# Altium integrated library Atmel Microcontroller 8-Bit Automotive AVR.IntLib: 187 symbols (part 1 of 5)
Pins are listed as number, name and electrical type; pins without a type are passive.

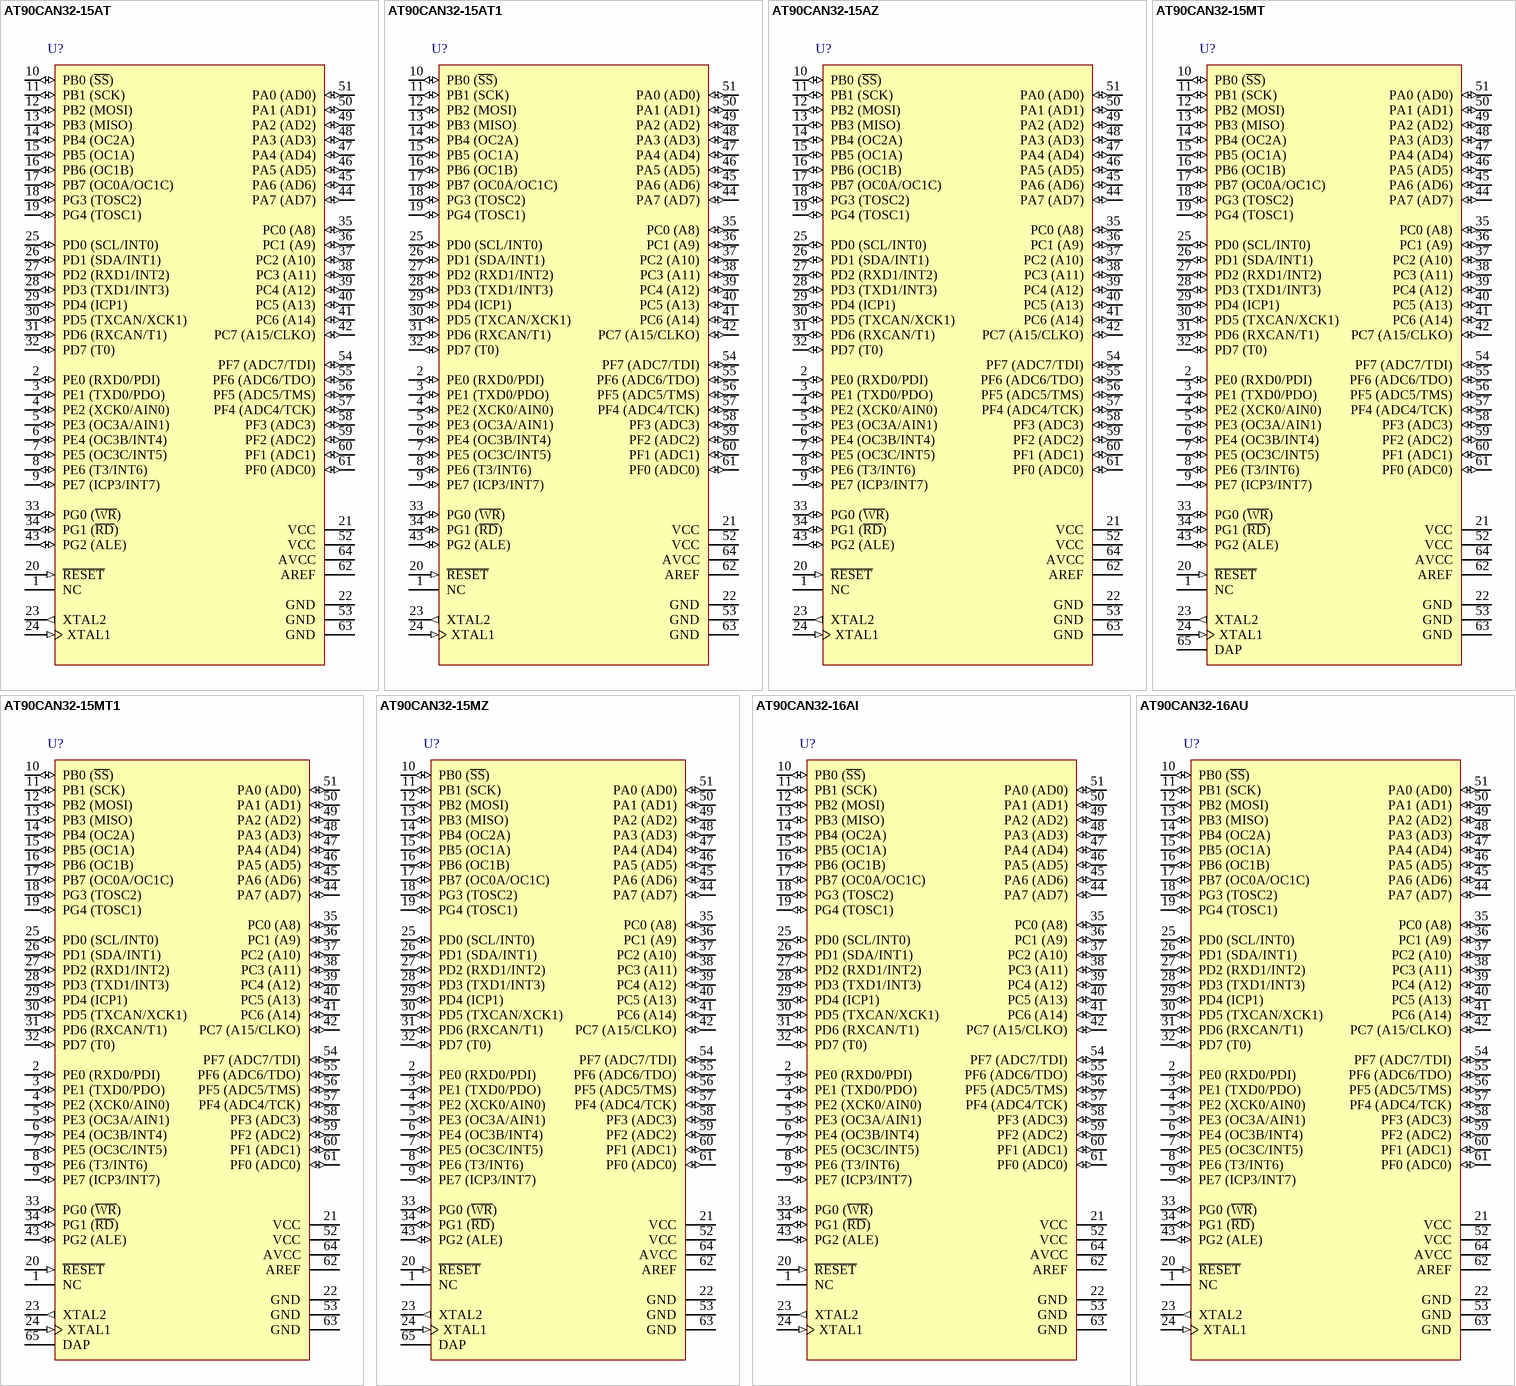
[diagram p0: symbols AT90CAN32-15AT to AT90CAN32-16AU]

## AT90CAN32-15AT
designator U?
8-bit Automotive AVR Microcontroller, 32KB Flash and CAN Controller, 53 GPIO pins, Automotive Grade (-40°to +85°C), 64-pin LQFP
footprint 64A_N (Thin QFP, 64-Leads, Body 14x14mm, Pitch 0.8mm, IPC Medium Density)
footprint 64A_L (Thin QFP, 64-Leads, Body 14x14mm, Pitch 0.8mm, IPC High Density)
footprint 64A_M (Thin QFP, 64-Leads, Body 14x14mm, Pitch 0.8mm, IPC Low Density)
pins: 1 NC, 2 PE0 (RXD0/PDI) (io), 3 PE1 (TXD0/PDO) (io), 4 PE2 (XCK0/AIN0) (io), 5 PE3 (OC3A/AIN1) (io), 6 PE4 (OC3B/INT4) (io), 7 PE5 (OC3C/INT5) (io), 8 PE6 (T3/INT6) (io), 9 PE7 (ICP3/INT7) (io), 10 PB0 (~{SS}) (io), 11 PB1 (SCK) (io), 12 PB2 (MOSI) (io), 13 PB3 (MISO) (io), 14 PB4 (OC2A) (io), 15 PB5 (OC1A) (io), 16 PB6 (OC1B) (io), 17 PB7 (OC0A/OC1C) (io), 18 PG3 (TOSC2) (io), 19 PG4 (TOSC1) (io), 20 ~{RESET} (in), 21 VCC (power), 22 GND (power), 23 XTAL2 (out), 24 XTAL1 (in), 25 PD0 (SCL/INT0) (io), 26 PD1 (SDA/INT1) (io), 27 PD2 (RXD1/INT2) (io), 28 PD3 (TXD1/INT3) (io), 29 PD4 (ICP1) (io), 30 PD5 (TXCAN/XCK1) (io), 31 PD6 (RXCAN/T1) (io), 32 PD7 (T0) (io), 33 PG0 (~{WR}) (io), 34 PG1 (~{RD}) (io), 35 PC0 (A8) (io), 36 PC1 (A9) (io), 37 PC2 (A10) (io), 38 PC3 (A11) (io), 39 PC4 (A12) (io), 40 PC5 (A13) (io), 41 PC6 (A14) (io), 42 PC7 (A15/CLKO) (io), 43 PG2 (ALE) (io), 44 PA7 (AD7) (io), 45 PA6 (AD6) (io), 46 PA5 (AD5) (io), 47 PA4 (AD4) (io), 48 PA3 (AD3) (io), 49 PA2 (AD2) (io), 50 PA1 (AD1) (io), 51 PA0 (AD0) (io), 52 VCC (power), 53 GND (power), 54 PF7 (ADC7/TDI) (io), 55 PF6 (ADC6/TDO) (io), 56 PF5 (ADC5/TMS) (io), 57 PF4 (ADC4/TCK) (io), 58 PF3 (ADC3) (io), 59 PF2 (ADC2) (io), 60 PF1 (ADC1) (io), 61 PF0 (ADC0) (io), 62 AREF (power), 63 GND (power), 64 AVCC (power)

## AT90CAN32-15AT1
designator U?
8-bit Automotive AVR Microcontroller, 32KB Flash and CAN Controller, 53 GPIO pins, Automotive Grade (-40°to +105°C), 64-pin LQFP
footprint 64A_N (Thin QFP, 64-Leads, Body 14x14mm, Pitch 0.8mm, IPC Medium Density)
footprint 64A_L (Thin QFP, 64-Leads, Body 14x14mm, Pitch 0.8mm, IPC High Density)
footprint 64A_M (Thin QFP, 64-Leads, Body 14x14mm, Pitch 0.8mm, IPC Low Density)
pins: 1 NC, 2 PE0 (RXD0/PDI) (io), 3 PE1 (TXD0/PDO) (io), 4 PE2 (XCK0/AIN0) (io), 5 PE3 (OC3A/AIN1) (io), 6 PE4 (OC3B/INT4) (io), 7 PE5 (OC3C/INT5) (io), 8 PE6 (T3/INT6) (io), 9 PE7 (ICP3/INT7) (io), 10 PB0 (~{SS}) (io), 11 PB1 (SCK) (io), 12 PB2 (MOSI) (io), 13 PB3 (MISO) (io), 14 PB4 (OC2A) (io), 15 PB5 (OC1A) (io), 16 PB6 (OC1B) (io), 17 PB7 (OC0A/OC1C) (io), 18 PG3 (TOSC2) (io), 19 PG4 (TOSC1) (io), 20 ~{RESET} (in), 21 VCC (power), 22 GND (power), 23 XTAL2 (out), 24 XTAL1 (in), 25 PD0 (SCL/INT0) (io), 26 PD1 (SDA/INT1) (io), 27 PD2 (RXD1/INT2) (io), 28 PD3 (TXD1/INT3) (io), 29 PD4 (ICP1) (io), 30 PD5 (TXCAN/XCK1) (io), 31 PD6 (RXCAN/T1) (io), 32 PD7 (T0) (io), 33 PG0 (~{WR}) (io), 34 PG1 (~{RD}) (io), 35 PC0 (A8) (io), 36 PC1 (A9) (io), 37 PC2 (A10) (io), 38 PC3 (A11) (io), 39 PC4 (A12) (io), 40 PC5 (A13) (io), 41 PC6 (A14) (io), 42 PC7 (A15/CLKO) (io), 43 PG2 (ALE) (io), 44 PA7 (AD7) (io), 45 PA6 (AD6) (io), 46 PA5 (AD5) (io), 47 PA4 (AD4) (io), 48 PA3 (AD3) (io), 49 PA2 (AD2) (io), 50 PA1 (AD1) (io), 51 PA0 (AD0) (io), 52 VCC (power), 53 GND (power), 54 PF7 (ADC7/TDI) (io), 55 PF6 (ADC6/TDO) (io), 56 PF5 (ADC5/TMS) (io), 57 PF4 (ADC4/TCK) (io), 58 PF3 (ADC3) (io), 59 PF2 (ADC2) (io), 60 PF1 (ADC1) (io), 61 PF0 (ADC0) (io), 62 AREF (power), 63 GND (power), 64 AVCC (power)

## AT90CAN32-15AZ
designator U?
8-bit Automotive AVR Microcontroller, 32KB Flash and CAN Controller, 53 GPIO pins, Automotive Grade (-40°to +125°C), 64-pin LQFP
footprint 64A_N (Thin QFP, 64-Leads, Body 14x14mm, Pitch 0.8mm, IPC Medium Density)
footprint 64A_L (Thin QFP, 64-Leads, Body 14x14mm, Pitch 0.8mm, IPC High Density)
footprint 64A_M (Thin QFP, 64-Leads, Body 14x14mm, Pitch 0.8mm, IPC Low Density)
pins: 1 NC, 2 PE0 (RXD0/PDI) (io), 3 PE1 (TXD0/PDO) (io), 4 PE2 (XCK0/AIN0) (io), 5 PE3 (OC3A/AIN1) (io), 6 PE4 (OC3B/INT4) (io), 7 PE5 (OC3C/INT5) (io), 8 PE6 (T3/INT6) (io), 9 PE7 (ICP3/INT7) (io), 10 PB0 (~{SS}) (io), 11 PB1 (SCK) (io), 12 PB2 (MOSI) (io), 13 PB3 (MISO) (io), 14 PB4 (OC2A) (io), 15 PB5 (OC1A) (io), 16 PB6 (OC1B) (io), 17 PB7 (OC0A/OC1C) (io), 18 PG3 (TOSC2) (io), 19 PG4 (TOSC1) (io), 20 ~{RESET} (in), 21 VCC (power), 22 GND (power), 23 XTAL2 (out), 24 XTAL1 (in), 25 PD0 (SCL/INT0) (io), 26 PD1 (SDA/INT1) (io), 27 PD2 (RXD1/INT2) (io), 28 PD3 (TXD1/INT3) (io), 29 PD4 (ICP1) (io), 30 PD5 (TXCAN/XCK1) (io), 31 PD6 (RXCAN/T1) (io), 32 PD7 (T0) (io), 33 PG0 (~{WR}) (io), 34 PG1 (~{RD}) (io), 35 PC0 (A8) (io), 36 PC1 (A9) (io), 37 PC2 (A10) (io), 38 PC3 (A11) (io), 39 PC4 (A12) (io), 40 PC5 (A13) (io), 41 PC6 (A14) (io), 42 PC7 (A15/CLKO) (io), 43 PG2 (ALE) (io), 44 PA7 (AD7) (io), 45 PA6 (AD6) (io), 46 PA5 (AD5) (io), 47 PA4 (AD4) (io), 48 PA3 (AD3) (io), 49 PA2 (AD2) (io), 50 PA1 (AD1) (io), 51 PA0 (AD0) (io), 52 VCC (power), 53 GND (power), 54 PF7 (ADC7/TDI) (io), 55 PF6 (ADC6/TDO) (io), 56 PF5 (ADC5/TMS) (io), 57 PF4 (ADC4/TCK) (io), 58 PF3 (ADC3) (io), 59 PF2 (ADC2) (io), 60 PF1 (ADC1) (io), 61 PF0 (ADC0) (io), 62 AREF (power), 63 GND (power), 64 AVCC (power)

## AT90CAN32-15MT
designator U?
8-bit Automotive AVR Microcontroller, 32KB Flash and CAN Controller, 53 GPIO pins, Automotive Grade (-40°to +85°C), 64-Pin VQFN
footprint Z64-1_N (QFN, 64-Leads, Body 9x9mm, Pitch 0.5mm, IPC Medium Density)
footprint Z64-1_L (QFN, 64-Leads, Body 9x9mm, Pitch 0.5mm, IPC High Density)
footprint Z64-1_M (QFN, 64-Leads, Body 9x9mm, Pitch 0.5mm, IPC Low Density)
pins: 1 NC, 2 PE0 (RXD0/PDI) (io), 3 PE1 (TXD0/PDO) (io), 4 PE2 (XCK0/AIN0) (io), 5 PE3 (OC3A/AIN1) (io), 6 PE4 (OC3B/INT4) (io), 7 PE5 (OC3C/INT5) (io), 8 PE6 (T3/INT6) (io), 9 PE7 (ICP3/INT7) (io), 10 PB0 (~{SS}) (io), 11 PB1 (SCK) (io), 12 PB2 (MOSI) (io), 13 PB3 (MISO) (io), 14 PB4 (OC2A) (io), 15 PB5 (OC1A) (io), 16 PB6 (OC1B) (io), 17 PB7 (OC0A/OC1C) (io), 18 PG3 (TOSC2) (io), 19 PG4 (TOSC1) (io), 20 ~{RESET} (in), 21 VCC (power), 22 GND (power), 23 XTAL2 (out), 24 XTAL1 (in), 25 PD0 (SCL/INT0) (io), 26 PD1 (SDA/INT1) (io), 27 PD2 (RXD1/INT2) (io), 28 PD3 (TXD1/INT3) (io), 29 PD4 (ICP1) (io), 30 PD5 (TXCAN/XCK1) (io), 31 PD6 (RXCAN/T1) (io), 32 PD7 (T0) (io), 33 PG0 (~{WR}) (io), 34 PG1 (~{RD}) (io), 35 PC0 (A8) (io), 36 PC1 (A9) (io), 37 PC2 (A10) (io), 38 PC3 (A11) (io), 39 PC4 (A12) (io), 40 PC5 (A13) (io), 41 PC6 (A14) (io), 42 PC7 (A15/CLKO) (io), 43 PG2 (ALE) (io), 44 PA7 (AD7) (io), 45 PA6 (AD6) (io), 46 PA5 (AD5) (io), 47 PA4 (AD4) (io), 48 PA3 (AD3) (io), 49 PA2 (AD2) (io), 50 PA1 (AD1) (io), 51 PA0 (AD0) (io), 52 VCC (power), 53 GND (power), 54 PF7 (ADC7/TDI) (io), 55 PF6 (ADC6/TDO) (io), 56 PF5 (ADC5/TMS) (io), 57 PF4 (ADC4/TCK) (io), 58 PF3 (ADC3) (io), 59 PF2 (ADC2) (io), 60 PF1 (ADC1) (io), 61 PF0 (ADC0) (io), 62 AREF (power), 63 GND (power), 64 AVCC (power), 65 DAP (power)

## AT90CAN32-15MT1
designator U?
8-bit Automotive AVR Microcontroller, 32KB Flash and CAN Controller, 53 GPIO pins, Automotive Grade (-40°to +105C), 64-Pin VQFN
footprint Z64-1_N (QFN, 64-Leads, Body 9x9mm, Pitch 0.5mm, IPC Medium Density)
footprint Z64-1_L (QFN, 64-Leads, Body 9x9mm, Pitch 0.5mm, IPC High Density)
footprint Z64-1_M (QFN, 64-Leads, Body 9x9mm, Pitch 0.5mm, IPC Low Density)
pins: 1 NC, 2 PE0 (RXD0/PDI) (io), 3 PE1 (TXD0/PDO) (io), 4 PE2 (XCK0/AIN0) (io), 5 PE3 (OC3A/AIN1) (io), 6 PE4 (OC3B/INT4) (io), 7 PE5 (OC3C/INT5) (io), 8 PE6 (T3/INT6) (io), 9 PE7 (ICP3/INT7) (io), 10 PB0 (~{SS}) (io), 11 PB1 (SCK) (io), 12 PB2 (MOSI) (io), 13 PB3 (MISO) (io), 14 PB4 (OC2A) (io), 15 PB5 (OC1A) (io), 16 PB6 (OC1B) (io), 17 PB7 (OC0A/OC1C) (io), 18 PG3 (TOSC2) (io), 19 PG4 (TOSC1) (io), 20 ~{RESET} (in), 21 VCC (power), 22 GND (power), 23 XTAL2 (out), 24 XTAL1 (in), 25 PD0 (SCL/INT0) (io), 26 PD1 (SDA/INT1) (io), 27 PD2 (RXD1/INT2) (io), 28 PD3 (TXD1/INT3) (io), 29 PD4 (ICP1) (io), 30 PD5 (TXCAN/XCK1) (io), 31 PD6 (RXCAN/T1) (io), 32 PD7 (T0) (io), 33 PG0 (~{WR}) (io), 34 PG1 (~{RD}) (io), 35 PC0 (A8) (io), 36 PC1 (A9) (io), 37 PC2 (A10) (io), 38 PC3 (A11) (io), 39 PC4 (A12) (io), 40 PC5 (A13) (io), 41 PC6 (A14) (io), 42 PC7 (A15/CLKO) (io), 43 PG2 (ALE) (io), 44 PA7 (AD7) (io), 45 PA6 (AD6) (io), 46 PA5 (AD5) (io), 47 PA4 (AD4) (io), 48 PA3 (AD3) (io), 49 PA2 (AD2) (io), 50 PA1 (AD1) (io), 51 PA0 (AD0) (io), 52 VCC (power), 53 GND (power), 54 PF7 (ADC7/TDI) (io), 55 PF6 (ADC6/TDO) (io), 56 PF5 (ADC5/TMS) (io), 57 PF4 (ADC4/TCK) (io), 58 PF3 (ADC3) (io), 59 PF2 (ADC2) (io), 60 PF1 (ADC1) (io), 61 PF0 (ADC0) (io), 62 AREF (power), 63 GND (power), 64 AVCC (power), 65 DAP (power)

## AT90CAN32-15MZ
designator U?
8-bit Automotive AVR Microcontroller, 32KB Flash and CAN Controller, 53 GPIO pins, Automotive Grade (-40°to +125°C), 64-Pin VQFN
footprint Z64-1_N (QFN, 64-Leads, Body 9x9mm, Pitch 0.5mm, IPC Medium Density)
footprint Z64-1_L (QFN, 64-Leads, Body 9x9mm, Pitch 0.5mm, IPC High Density)
footprint Z64-1_M (QFN, 64-Leads, Body 9x9mm, Pitch 0.5mm, IPC Low Density)
pins: 1 NC, 2 PE0 (RXD0/PDI) (io), 3 PE1 (TXD0/PDO) (io), 4 PE2 (XCK0/AIN0) (io), 5 PE3 (OC3A/AIN1) (io), 6 PE4 (OC3B/INT4) (io), 7 PE5 (OC3C/INT5) (io), 8 PE6 (T3/INT6) (io), 9 PE7 (ICP3/INT7) (io), 10 PB0 (~{SS}) (io), 11 PB1 (SCK) (io), 12 PB2 (MOSI) (io), 13 PB3 (MISO) (io), 14 PB4 (OC2A) (io), 15 PB5 (OC1A) (io), 16 PB6 (OC1B) (io), 17 PB7 (OC0A/OC1C) (io), 18 PG3 (TOSC2) (io), 19 PG4 (TOSC1) (io), 20 ~{RESET} (in), 21 VCC (power), 22 GND (power), 23 XTAL2 (out), 24 XTAL1 (in), 25 PD0 (SCL/INT0) (io), 26 PD1 (SDA/INT1) (io), 27 PD2 (RXD1/INT2) (io), 28 PD3 (TXD1/INT3) (io), 29 PD4 (ICP1) (io), 30 PD5 (TXCAN/XCK1) (io), 31 PD6 (RXCAN/T1) (io), 32 PD7 (T0) (io), 33 PG0 (~{WR}) (io), 34 PG1 (~{RD}) (io), 35 PC0 (A8) (io), 36 PC1 (A9) (io), 37 PC2 (A10) (io), 38 PC3 (A11) (io), 39 PC4 (A12) (io), 40 PC5 (A13) (io), 41 PC6 (A14) (io), 42 PC7 (A15/CLKO) (io), 43 PG2 (ALE) (io), 44 PA7 (AD7) (io), 45 PA6 (AD6) (io), 46 PA5 (AD5) (io), 47 PA4 (AD4) (io), 48 PA3 (AD3) (io), 49 PA2 (AD2) (io), 50 PA1 (AD1) (io), 51 PA0 (AD0) (io), 52 VCC (power), 53 GND (power), 54 PF7 (ADC7/TDI) (io), 55 PF6 (ADC6/TDO) (io), 56 PF5 (ADC5/TMS) (io), 57 PF4 (ADC4/TCK) (io), 58 PF3 (ADC3) (io), 59 PF2 (ADC2) (io), 60 PF1 (ADC1) (io), 61 PF0 (ADC0) (io), 62 AREF (power), 63 GND (power), 64 AVCC (power), 65 DAP (power)

## AT90CAN32-16AI
designator U?
8-bit AVR Microcontroller, 32KB Flash and CAN Controller, 53 GPIO pins, Industrial Grade (-40° to +85°C), 64-pin LQFP
footprint 64A_N (Thin QFP, 64-Leads, Body 14x14mm, Pitch 0.8mm, IPC Medium Density)
footprint 64A_L (Thin QFP, 64-Leads, Body 14x14mm, Pitch 0.8mm, IPC High Density)
footprint 64A_M (Thin QFP, 64-Leads, Body 14x14mm, Pitch 0.8mm, IPC Low Density)
pins: 1 NC, 2 PE0 (RXD0/PDI) (io), 3 PE1 (TXD0/PDO) (io), 4 PE2 (XCK0/AIN0) (io), 5 PE3 (OC3A/AIN1) (io), 6 PE4 (OC3B/INT4) (io), 7 PE5 (OC3C/INT5) (io), 8 PE6 (T3/INT6) (io), 9 PE7 (ICP3/INT7) (io), 10 PB0 (~{SS}) (io), 11 PB1 (SCK) (io), 12 PB2 (MOSI) (io), 13 PB3 (MISO) (io), 14 PB4 (OC2A) (io), 15 PB5 (OC1A) (io), 16 PB6 (OC1B) (io), 17 PB7 (OC0A/OC1C) (io), 18 PG3 (TOSC2) (io), 19 PG4 (TOSC1) (io), 20 ~{RESET} (in), 21 VCC (power), 22 GND (power), 23 XTAL2 (out), 24 XTAL1 (in), 25 PD0 (SCL/INT0) (io), 26 PD1 (SDA/INT1) (io), 27 PD2 (RXD1/INT2) (io), 28 PD3 (TXD1/INT3) (io), 29 PD4 (ICP1) (io), 30 PD5 (TXCAN/XCK1) (io), 31 PD6 (RXCAN/T1) (io), 32 PD7 (T0) (io), 33 PG0 (~{WR}) (io), 34 PG1 (~{RD}) (io), 35 PC0 (A8) (io), 36 PC1 (A9) (io), 37 PC2 (A10) (io), 38 PC3 (A11) (io), 39 PC4 (A12) (io), 40 PC5 (A13) (io), 41 PC6 (A14) (io), 42 PC7 (A15/CLKO) (io), 43 PG2 (ALE) (io), 44 PA7 (AD7) (io), 45 PA6 (AD6) (io), 46 PA5 (AD5) (io), 47 PA4 (AD4) (io), 48 PA3 (AD3) (io), 49 PA2 (AD2) (io), 50 PA1 (AD1) (io), 51 PA0 (AD0) (io), 52 VCC (power), 53 GND (power), 54 PF7 (ADC7/TDI) (io), 55 PF6 (ADC6/TDO) (io), 56 PF5 (ADC5/TMS) (io), 57 PF4 (ADC4/TCK) (io), 58 PF3 (ADC3) (io), 59 PF2 (ADC2) (io), 60 PF1 (ADC1) (io), 61 PF0 (ADC0) (io), 62 AREF (power), 63 GND (power), 64 AVCC (power)

## AT90CAN32-16AU
designator U?
8-bit AVR Microcontroller, 32KB Flash and CAN Controller, 53 GPIO pins, Industrial Grade (-40° to +85°C), 64-pin LQFP, Green
footprint 64A_N (Thin QFP, 64-Leads, Body 14x14mm, Pitch 0.8mm, IPC Medium Density)
footprint 64A_L (Thin QFP, 64-Leads, Body 14x14mm, Pitch 0.8mm, IPC High Density)
footprint 64A_M (Thin QFP, 64-Leads, Body 14x14mm, Pitch 0.8mm, IPC Low Density)
pins: 1 NC, 2 PE0 (RXD0/PDI) (io), 3 PE1 (TXD0/PDO) (io), 4 PE2 (XCK0/AIN0) (io), 5 PE3 (OC3A/AIN1) (io), 6 PE4 (OC3B/INT4) (io), 7 PE5 (OC3C/INT5) (io), 8 PE6 (T3/INT6) (io), 9 PE7 (ICP3/INT7) (io), 10 PB0 (~{SS}) (io), 11 PB1 (SCK) (io), 12 PB2 (MOSI) (io), 13 PB3 (MISO) (io), 14 PB4 (OC2A) (io), 15 PB5 (OC1A) (io), 16 PB6 (OC1B) (io), 17 PB7 (OC0A/OC1C) (io), 18 PG3 (TOSC2) (io), 19 PG4 (TOSC1) (io), 20 ~{RESET} (in), 21 VCC (power), 22 GND (power), 23 XTAL2 (out), 24 XTAL1 (in), 25 PD0 (SCL/INT0) (io), 26 PD1 (SDA/INT1) (io), 27 PD2 (RXD1/INT2) (io), 28 PD3 (TXD1/INT3) (io), 29 PD4 (ICP1) (io), 30 PD5 (TXCAN/XCK1) (io), 31 PD6 (RXCAN/T1) (io), 32 PD7 (T0) (io), 33 PG0 (~{WR}) (io), 34 PG1 (~{RD}) (io), 35 PC0 (A8) (io), 36 PC1 (A9) (io), 37 PC2 (A10) (io), 38 PC3 (A11) (io), 39 PC4 (A12) (io), 40 PC5 (A13) (io), 41 PC6 (A14) (io), 42 PC7 (A15/CLKO) (io), 43 PG2 (ALE) (io), 44 PA7 (AD7) (io), 45 PA6 (AD6) (io), 46 PA5 (AD5) (io), 47 PA4 (AD4) (io), 48 PA3 (AD3) (io), 49 PA2 (AD2) (io), 50 PA1 (AD1) (io), 51 PA0 (AD0) (io), 52 VCC (power), 53 GND (power), 54 PF7 (ADC7/TDI) (io), 55 PF6 (ADC6/TDO) (io), 56 PF5 (ADC5/TMS) (io), 57 PF4 (ADC4/TCK) (io), 58 PF3 (ADC3) (io), 59 PF2 (ADC2) (io), 60 PF1 (ADC1) (io), 61 PF0 (ADC0) (io), 62 AREF (power), 63 GND (power), 64 AVCC (power)

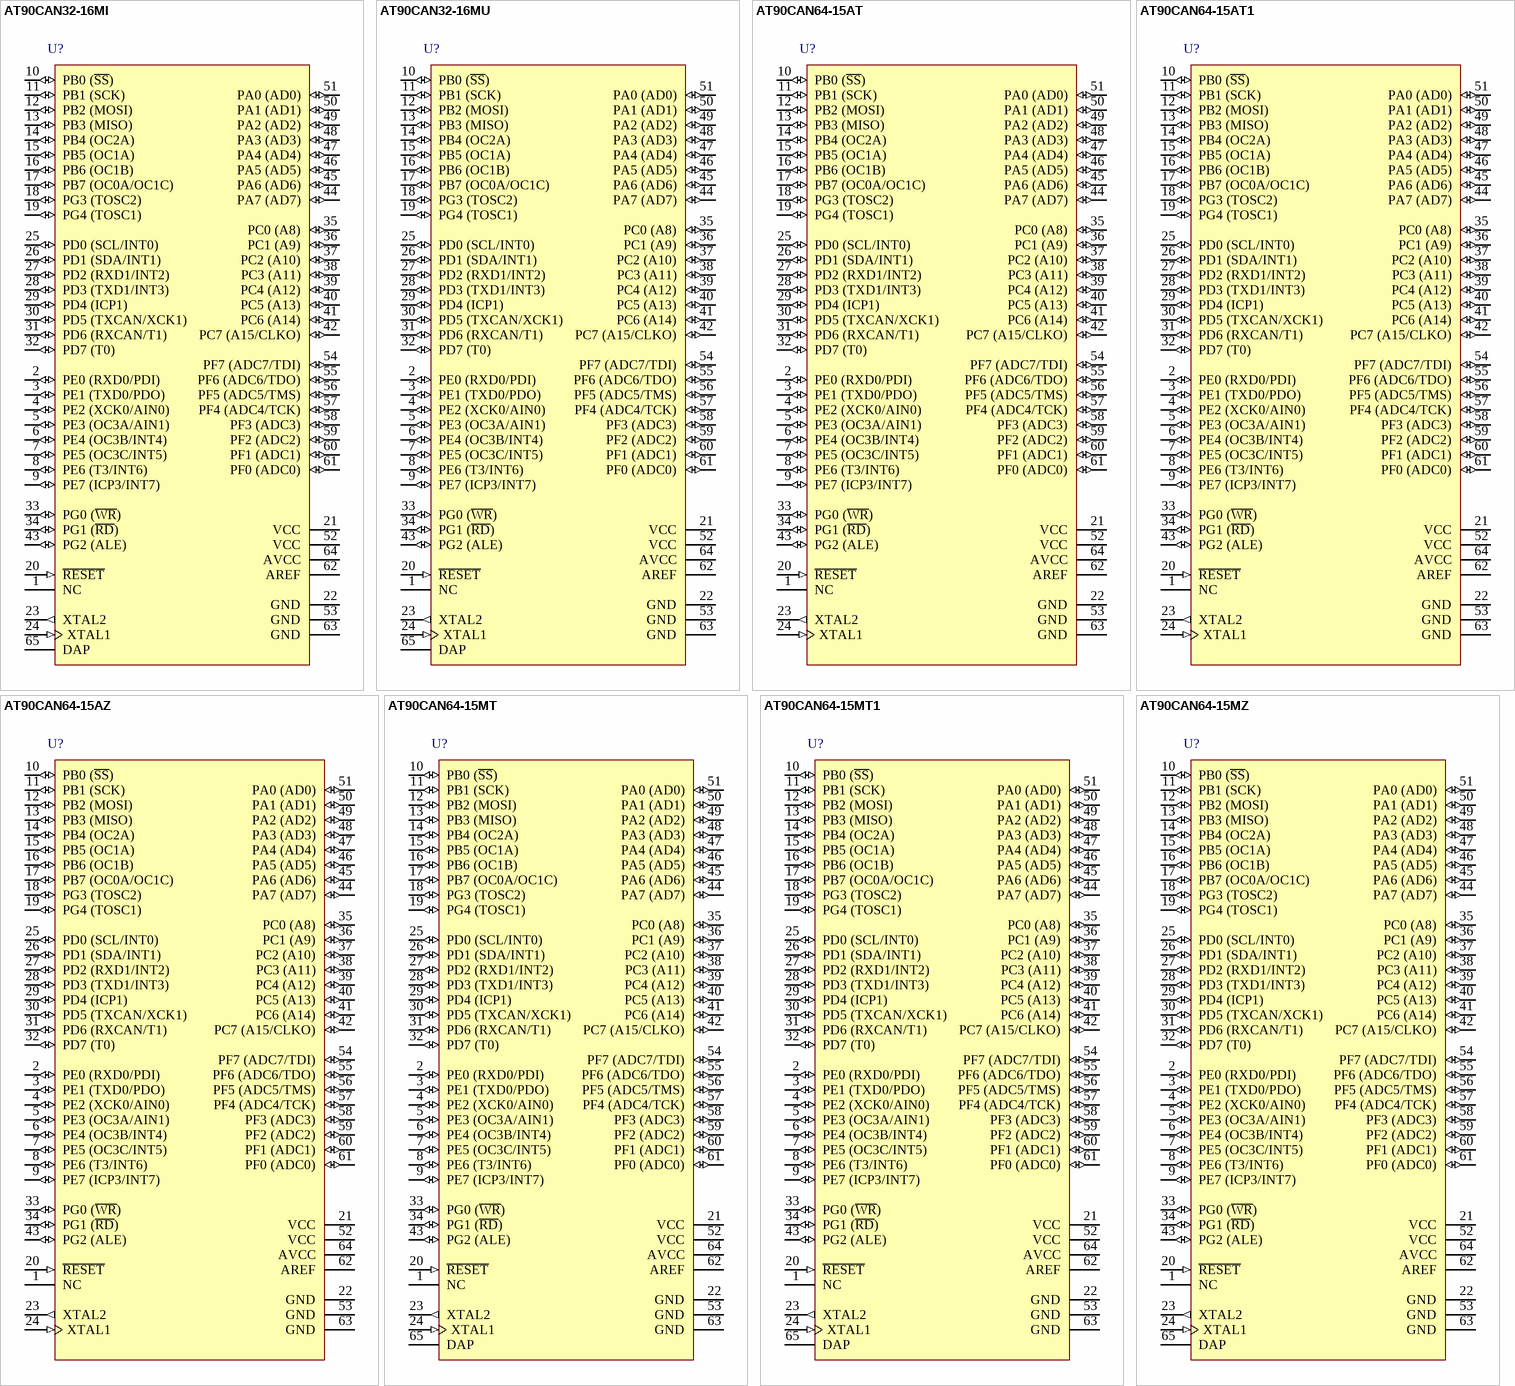
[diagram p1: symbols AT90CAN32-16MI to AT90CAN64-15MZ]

## AT90CAN32-16MI
designator U?
8-bit AVR Microcontroller, 32KB Flash and CAN Controller, 53 GPIO pins, Industrial Grade (-40° to +85°C), 64-pin VQFN
footprint Z64-1_N (QFN, 64-Leads, Body 9x9mm, Pitch 0.5mm, IPC Medium Density)
footprint Z64-1_L (QFN, 64-Leads, Body 9x9mm, Pitch 0.5mm, IPC High Density)
footprint Z64-1_M (QFN, 64-Leads, Body 9x9mm, Pitch 0.5mm, IPC Low Density)
pins: 1 NC, 2 PE0 (RXD0/PDI) (io), 3 PE1 (TXD0/PDO) (io), 4 PE2 (XCK0/AIN0) (io), 5 PE3 (OC3A/AIN1) (io), 6 PE4 (OC3B/INT4) (io), 7 PE5 (OC3C/INT5) (io), 8 PE6 (T3/INT6) (io), 9 PE7 (ICP3/INT7) (io), 10 PB0 (~{SS}) (io), 11 PB1 (SCK) (io), 12 PB2 (MOSI) (io), 13 PB3 (MISO) (io), 14 PB4 (OC2A) (io), 15 PB5 (OC1A) (io), 16 PB6 (OC1B) (io), 17 PB7 (OC0A/OC1C) (io), 18 PG3 (TOSC2) (io), 19 PG4 (TOSC1) (io), 20 ~{RESET} (in), 21 VCC (power), 22 GND (power), 23 XTAL2 (out), 24 XTAL1 (in), 25 PD0 (SCL/INT0) (io), 26 PD1 (SDA/INT1) (io), 27 PD2 (RXD1/INT2) (io), 28 PD3 (TXD1/INT3) (io), 29 PD4 (ICP1) (io), 30 PD5 (TXCAN/XCK1) (io), 31 PD6 (RXCAN/T1) (io), 32 PD7 (T0) (io), 33 PG0 (~{WR}) (io), 34 PG1 (~{RD}) (io), 35 PC0 (A8) (io), 36 PC1 (A9) (io), 37 PC2 (A10) (io), 38 PC3 (A11) (io), 39 PC4 (A12) (io), 40 PC5 (A13) (io), 41 PC6 (A14) (io), 42 PC7 (A15/CLKO) (io), 43 PG2 (ALE) (io), 44 PA7 (AD7) (io), 45 PA6 (AD6) (io), 46 PA5 (AD5) (io), 47 PA4 (AD4) (io), 48 PA3 (AD3) (io), 49 PA2 (AD2) (io), 50 PA1 (AD1) (io), 51 PA0 (AD0) (io), 52 VCC (power), 53 GND (power), 54 PF7 (ADC7/TDI) (io), 55 PF6 (ADC6/TDO) (io), 56 PF5 (ADC5/TMS) (io), 57 PF4 (ADC4/TCK) (io), 58 PF3 (ADC3) (io), 59 PF2 (ADC2) (io), 60 PF1 (ADC1) (io), 61 PF0 (ADC0) (io), 62 AREF (power), 63 GND (power), 64 AVCC (power), 65 DAP (power)

## AT90CAN32-16MU
designator U?
8-bit AVR Microcontroller, 32KB Flash and CAN Controller, 53 GPIO pins, Industrial Grade (-40° to +85°C), 64-pin VQFN, Green
footprint Z64-1_N (QFN, 64-Leads, Body 9x9mm, Pitch 0.5mm, IPC Medium Density)
footprint Z64-1_L (QFN, 64-Leads, Body 9x9mm, Pitch 0.5mm, IPC High Density)
footprint Z64-1_M (QFN, 64-Leads, Body 9x9mm, Pitch 0.5mm, IPC Low Density)
pins: 1 NC, 2 PE0 (RXD0/PDI) (io), 3 PE1 (TXD0/PDO) (io), 4 PE2 (XCK0/AIN0) (io), 5 PE3 (OC3A/AIN1) (io), 6 PE4 (OC3B/INT4) (io), 7 PE5 (OC3C/INT5) (io), 8 PE6 (T3/INT6) (io), 9 PE7 (ICP3/INT7) (io), 10 PB0 (~{SS}) (io), 11 PB1 (SCK) (io), 12 PB2 (MOSI) (io), 13 PB3 (MISO) (io), 14 PB4 (OC2A) (io), 15 PB5 (OC1A) (io), 16 PB6 (OC1B) (io), 17 PB7 (OC0A/OC1C) (io), 18 PG3 (TOSC2) (io), 19 PG4 (TOSC1) (io), 20 ~{RESET} (in), 21 VCC (power), 22 GND (power), 23 XTAL2 (out), 24 XTAL1 (in), 25 PD0 (SCL/INT0) (io), 26 PD1 (SDA/INT1) (io), 27 PD2 (RXD1/INT2) (io), 28 PD3 (TXD1/INT3) (io), 29 PD4 (ICP1) (io), 30 PD5 (TXCAN/XCK1) (io), 31 PD6 (RXCAN/T1) (io), 32 PD7 (T0) (io), 33 PG0 (~{WR}) (io), 34 PG1 (~{RD}) (io), 35 PC0 (A8) (io), 36 PC1 (A9) (io), 37 PC2 (A10) (io), 38 PC3 (A11) (io), 39 PC4 (A12) (io), 40 PC5 (A13) (io), 41 PC6 (A14) (io), 42 PC7 (A15/CLKO) (io), 43 PG2 (ALE) (io), 44 PA7 (AD7) (io), 45 PA6 (AD6) (io), 46 PA5 (AD5) (io), 47 PA4 (AD4) (io), 48 PA3 (AD3) (io), 49 PA2 (AD2) (io), 50 PA1 (AD1) (io), 51 PA0 (AD0) (io), 52 VCC (power), 53 GND (power), 54 PF7 (ADC7/TDI) (io), 55 PF6 (ADC6/TDO) (io), 56 PF5 (ADC5/TMS) (io), 57 PF4 (ADC4/TCK) (io), 58 PF3 (ADC3) (io), 59 PF2 (ADC2) (io), 60 PF1 (ADC1) (io), 61 PF0 (ADC0) (io), 62 AREF (power), 63 GND (power), 64 AVCC (power), 65 DAP (power)

## AT90CAN64-15AT
designator U?
8-bit Automotive AVR Microcontroller, 64KB Flash and CAN Controller, 53 GPIO pins, Automotive Grade (-40°to +85°C), 64-pin LQFP
footprint 64A_N (Thin QFP, 64-Leads, Body 14x14mm, Pitch 0.8mm, IPC Medium Density)
footprint 64A_L (Thin QFP, 64-Leads, Body 14x14mm, Pitch 0.8mm, IPC High Density)
footprint 64A_M (Thin QFP, 64-Leads, Body 14x14mm, Pitch 0.8mm, IPC Low Density)
pins: 1 NC, 2 PE0 (RXD0/PDI) (io), 3 PE1 (TXD0/PDO) (io), 4 PE2 (XCK0/AIN0) (io), 5 PE3 (OC3A/AIN1) (io), 6 PE4 (OC3B/INT4) (io), 7 PE5 (OC3C/INT5) (io), 8 PE6 (T3/INT6) (io), 9 PE7 (ICP3/INT7) (io), 10 PB0 (~{SS}) (io), 11 PB1 (SCK) (io), 12 PB2 (MOSI) (io), 13 PB3 (MISO) (io), 14 PB4 (OC2A) (io), 15 PB5 (OC1A) (io), 16 PB6 (OC1B) (io), 17 PB7 (OC0A/OC1C) (io), 18 PG3 (TOSC2) (io), 19 PG4 (TOSC1) (io), 20 ~{RESET} (in), 21 VCC (power), 22 GND (power), 23 XTAL2 (out), 24 XTAL1 (in), 25 PD0 (SCL/INT0) (io), 26 PD1 (SDA/INT1) (io), 27 PD2 (RXD1/INT2) (io), 28 PD3 (TXD1/INT3) (io), 29 PD4 (ICP1) (io), 30 PD5 (TXCAN/XCK1) (io), 31 PD6 (RXCAN/T1) (io), 32 PD7 (T0) (io), 33 PG0 (~{WR}) (io), 34 PG1 (~{RD}) (io), 35 PC0 (A8) (io), 36 PC1 (A9) (io), 37 PC2 (A10) (io), 38 PC3 (A11) (io), 39 PC4 (A12) (io), 40 PC5 (A13) (io), 41 PC6 (A14) (io), 42 PC7 (A15/CLKO) (io), 43 PG2 (ALE) (io), 44 PA7 (AD7) (io), 45 PA6 (AD6) (io), 46 PA5 (AD5) (io), 47 PA4 (AD4) (io), 48 PA3 (AD3) (io), 49 PA2 (AD2) (io), 50 PA1 (AD1) (io), 51 PA0 (AD0) (io), 52 VCC (power), 53 GND (power), 54 PF7 (ADC7/TDI) (io), 55 PF6 (ADC6/TDO) (io), 56 PF5 (ADC5/TMS) (io), 57 PF4 (ADC4/TCK) (io), 58 PF3 (ADC3) (io), 59 PF2 (ADC2) (io), 60 PF1 (ADC1) (io), 61 PF0 (ADC0) (io), 62 AREF (power), 63 GND (power), 64 AVCC (power)

## AT90CAN64-15AT1
designator U?
8-bit Automotive AVR Microcontroller, 64KB Flash and CAN Controller, 53 GPIO pins, Automotive Grade (-40°to +105°C), 64-pin LQFP
footprint 64A_N (Thin QFP, 64-Leads, Body 14x14mm, Pitch 0.8mm, IPC Medium Density)
footprint 64A_L (Thin QFP, 64-Leads, Body 14x14mm, Pitch 0.8mm, IPC High Density)
footprint 64A_M (Thin QFP, 64-Leads, Body 14x14mm, Pitch 0.8mm, IPC Low Density)
pins: 1 NC, 2 PE0 (RXD0/PDI) (io), 3 PE1 (TXD0/PDO) (io), 4 PE2 (XCK0/AIN0) (io), 5 PE3 (OC3A/AIN1) (io), 6 PE4 (OC3B/INT4) (io), 7 PE5 (OC3C/INT5) (io), 8 PE6 (T3/INT6) (io), 9 PE7 (ICP3/INT7) (io), 10 PB0 (~{SS}) (io), 11 PB1 (SCK) (io), 12 PB2 (MOSI) (io), 13 PB3 (MISO) (io), 14 PB4 (OC2A) (io), 15 PB5 (OC1A) (io), 16 PB6 (OC1B) (io), 17 PB7 (OC0A/OC1C) (io), 18 PG3 (TOSC2) (io), 19 PG4 (TOSC1) (io), 20 ~{RESET} (in), 21 VCC (power), 22 GND (power), 23 XTAL2 (out), 24 XTAL1 (in), 25 PD0 (SCL/INT0) (io), 26 PD1 (SDA/INT1) (io), 27 PD2 (RXD1/INT2) (io), 28 PD3 (TXD1/INT3) (io), 29 PD4 (ICP1) (io), 30 PD5 (TXCAN/XCK1) (io), 31 PD6 (RXCAN/T1) (io), 32 PD7 (T0) (io), 33 PG0 (~{WR}) (io), 34 PG1 (~{RD}) (io), 35 PC0 (A8) (io), 36 PC1 (A9) (io), 37 PC2 (A10) (io), 38 PC3 (A11) (io), 39 PC4 (A12) (io), 40 PC5 (A13) (io), 41 PC6 (A14) (io), 42 PC7 (A15/CLKO) (io), 43 PG2 (ALE) (io), 44 PA7 (AD7) (io), 45 PA6 (AD6) (io), 46 PA5 (AD5) (io), 47 PA4 (AD4) (io), 48 PA3 (AD3) (io), 49 PA2 (AD2) (io), 50 PA1 (AD1) (io), 51 PA0 (AD0) (io), 52 VCC (power), 53 GND (power), 54 PF7 (ADC7/TDI) (io), 55 PF6 (ADC6/TDO) (io), 56 PF5 (ADC5/TMS) (io), 57 PF4 (ADC4/TCK) (io), 58 PF3 (ADC3) (io), 59 PF2 (ADC2) (io), 60 PF1 (ADC1) (io), 61 PF0 (ADC0) (io), 62 AREF (power), 63 GND (power), 64 AVCC (power)

## AT90CAN64-15AZ
designator U?
8-bit Automotive AVR Microcontroller, 64KB Flash and CAN Controller, 53 GPIO pins, Automotive Grade (-40°to +125°C), 64-pin LQFP
footprint 64A_N (Thin QFP, 64-Leads, Body 14x14mm, Pitch 0.8mm, IPC Medium Density)
footprint 64A_L (Thin QFP, 64-Leads, Body 14x14mm, Pitch 0.8mm, IPC High Density)
footprint 64A_M (Thin QFP, 64-Leads, Body 14x14mm, Pitch 0.8mm, IPC Low Density)
pins: 1 NC, 2 PE0 (RXD0/PDI) (io), 3 PE1 (TXD0/PDO) (io), 4 PE2 (XCK0/AIN0) (io), 5 PE3 (OC3A/AIN1) (io), 6 PE4 (OC3B/INT4) (io), 7 PE5 (OC3C/INT5) (io), 8 PE6 (T3/INT6) (io), 9 PE7 (ICP3/INT7) (io), 10 PB0 (~{SS}) (io), 11 PB1 (SCK) (io), 12 PB2 (MOSI) (io), 13 PB3 (MISO) (io), 14 PB4 (OC2A) (io), 15 PB5 (OC1A) (io), 16 PB6 (OC1B) (io), 17 PB7 (OC0A/OC1C) (io), 18 PG3 (TOSC2) (io), 19 PG4 (TOSC1) (io), 20 ~{RESET} (in), 21 VCC (power), 22 GND (power), 23 XTAL2 (out), 24 XTAL1 (in), 25 PD0 (SCL/INT0) (io), 26 PD1 (SDA/INT1) (io), 27 PD2 (RXD1/INT2) (io), 28 PD3 (TXD1/INT3) (io), 29 PD4 (ICP1) (io), 30 PD5 (TXCAN/XCK1) (io), 31 PD6 (RXCAN/T1) (io), 32 PD7 (T0) (io), 33 PG0 (~{WR}) (io), 34 PG1 (~{RD}) (io), 35 PC0 (A8) (io), 36 PC1 (A9) (io), 37 PC2 (A10) (io), 38 PC3 (A11) (io), 39 PC4 (A12) (io), 40 PC5 (A13) (io), 41 PC6 (A14) (io), 42 PC7 (A15/CLKO) (io), 43 PG2 (ALE) (io), 44 PA7 (AD7) (io), 45 PA6 (AD6) (io), 46 PA5 (AD5) (io), 47 PA4 (AD4) (io), 48 PA3 (AD3) (io), 49 PA2 (AD2) (io), 50 PA1 (AD1) (io), 51 PA0 (AD0) (io), 52 VCC (power), 53 GND (power), 54 PF7 (ADC7/TDI) (io), 55 PF6 (ADC6/TDO) (io), 56 PF5 (ADC5/TMS) (io), 57 PF4 (ADC4/TCK) (io), 58 PF3 (ADC3) (io), 59 PF2 (ADC2) (io), 60 PF1 (ADC1) (io), 61 PF0 (ADC0) (io), 62 AREF (power), 63 GND (power), 64 AVCC (power)

## AT90CAN64-15MT
designator U?
8-bit Automotive AVR Microcontroller, 64KB Flash and CAN Controller, 53 GPIO pins, Automotive Grade (-40°to +85°C), 64-Pin VQFN
footprint Z64-2_N (QFN, 64-Leads, Body 9x9mm, Pitch 0.5mm, IPC Medium Density)
footprint Z64-2_L (QFN, 64-Leads, Body 9x9mm, Pitch 0.5mm, IPC High Density)
footprint Z64-2_M (QFN, 64-Leads, Body 9x9mm, Pitch 0.5mm, IPC Low Density)
pins: 1 NC, 2 PE0 (RXD0/PDI) (io), 3 PE1 (TXD0/PDO) (io), 4 PE2 (XCK0/AIN0) (io), 5 PE3 (OC3A/AIN1) (io), 6 PE4 (OC3B/INT4) (io), 7 PE5 (OC3C/INT5) (io), 8 PE6 (T3/INT6) (io), 9 PE7 (ICP3/INT7) (io), 10 PB0 (~{SS}) (io), 11 PB1 (SCK) (io), 12 PB2 (MOSI) (io), 13 PB3 (MISO) (io), 14 PB4 (OC2A) (io), 15 PB5 (OC1A) (io), 16 PB6 (OC1B) (io), 17 PB7 (OC0A/OC1C) (io), 18 PG3 (TOSC2) (io), 19 PG4 (TOSC1) (io), 20 ~{RESET} (in), 21 VCC (power), 22 GND (power), 23 XTAL2 (out), 24 XTAL1 (in), 25 PD0 (SCL/INT0) (io), 26 PD1 (SDA/INT1) (io), 27 PD2 (RXD1/INT2) (io), 28 PD3 (TXD1/INT3) (io), 29 PD4 (ICP1) (io), 30 PD5 (TXCAN/XCK1) (io), 31 PD6 (RXCAN/T1) (io), 32 PD7 (T0) (io), 33 PG0 (~{WR}) (io), 34 PG1 (~{RD}) (io), 35 PC0 (A8) (io), 36 PC1 (A9) (io), 37 PC2 (A10) (io), 38 PC3 (A11) (io), 39 PC4 (A12) (io), 40 PC5 (A13) (io), 41 PC6 (A14) (io), 42 PC7 (A15/CLKO) (io), 43 PG2 (ALE) (io), 44 PA7 (AD7) (io), 45 PA6 (AD6) (io), 46 PA5 (AD5) (io), 47 PA4 (AD4) (io), 48 PA3 (AD3) (io), 49 PA2 (AD2) (io), 50 PA1 (AD1) (io), 51 PA0 (AD0) (io), 52 VCC (power), 53 GND (power), 54 PF7 (ADC7/TDI) (io), 55 PF6 (ADC6/TDO) (io), 56 PF5 (ADC5/TMS) (io), 57 PF4 (ADC4/TCK) (io), 58 PF3 (ADC3) (io), 59 PF2 (ADC2) (io), 60 PF1 (ADC1) (io), 61 PF0 (ADC0) (io), 62 AREF (power), 63 GND (power), 64 AVCC (power), 65 DAP (power)

## AT90CAN64-15MT1
designator U?
8-bit Automotive AVR Microcontroller, 64KB Flash and CAN Controller, 53 GPIO pins, Automotive Grade (-40°to +105C), 64-Pin VQFN
footprint Z64-2_N (QFN, 64-Leads, Body 9x9mm, Pitch 0.5mm, IPC Medium Density)
footprint Z64-2_L (QFN, 64-Leads, Body 9x9mm, Pitch 0.5mm, IPC High Density)
footprint Z64-2_M (QFN, 64-Leads, Body 9x9mm, Pitch 0.5mm, IPC Low Density)
pins: 1 NC, 2 PE0 (RXD0/PDI) (io), 3 PE1 (TXD0/PDO) (io), 4 PE2 (XCK0/AIN0) (io), 5 PE3 (OC3A/AIN1) (io), 6 PE4 (OC3B/INT4) (io), 7 PE5 (OC3C/INT5) (io), 8 PE6 (T3/INT6) (io), 9 PE7 (ICP3/INT7) (io), 10 PB0 (~{SS}) (io), 11 PB1 (SCK) (io), 12 PB2 (MOSI) (io), 13 PB3 (MISO) (io), 14 PB4 (OC2A) (io), 15 PB5 (OC1A) (io), 16 PB6 (OC1B) (io), 17 PB7 (OC0A/OC1C) (io), 18 PG3 (TOSC2) (io), 19 PG4 (TOSC1) (io), 20 ~{RESET} (in), 21 VCC (power), 22 GND (power), 23 XTAL2 (out), 24 XTAL1 (in), 25 PD0 (SCL/INT0) (io), 26 PD1 (SDA/INT1) (io), 27 PD2 (RXD1/INT2) (io), 28 PD3 (TXD1/INT3) (io), 29 PD4 (ICP1) (io), 30 PD5 (TXCAN/XCK1) (io), 31 PD6 (RXCAN/T1) (io), 32 PD7 (T0) (io), 33 PG0 (~{WR}) (io), 34 PG1 (~{RD}) (io), 35 PC0 (A8) (io), 36 PC1 (A9) (io), 37 PC2 (A10) (io), 38 PC3 (A11) (io), 39 PC4 (A12) (io), 40 PC5 (A13) (io), 41 PC6 (A14) (io), 42 PC7 (A15/CLKO) (io), 43 PG2 (ALE) (io), 44 PA7 (AD7) (io), 45 PA6 (AD6) (io), 46 PA5 (AD5) (io), 47 PA4 (AD4) (io), 48 PA3 (AD3) (io), 49 PA2 (AD2) (io), 50 PA1 (AD1) (io), 51 PA0 (AD0) (io), 52 VCC (power), 53 GND (power), 54 PF7 (ADC7/TDI) (io), 55 PF6 (ADC6/TDO) (io), 56 PF5 (ADC5/TMS) (io), 57 PF4 (ADC4/TCK) (io), 58 PF3 (ADC3) (io), 59 PF2 (ADC2) (io), 60 PF1 (ADC1) (io), 61 PF0 (ADC0) (io), 62 AREF (power), 63 GND (power), 64 AVCC (power), 65 DAP (power)

## AT90CAN64-15MZ
designator U?
8-bit Automotive AVR Microcontroller, 64KB Flash and CAN Controller, 53 GPIO pins, Automotive Grade (-40°to +125°C), 64-Pin VQFN
footprint Z64-2_N (QFN, 64-Leads, Body 9x9mm, Pitch 0.5mm, IPC Medium Density)
footprint Z64-2_L (QFN, 64-Leads, Body 9x9mm, Pitch 0.5mm, IPC High Density)
footprint Z64-2_M (QFN, 64-Leads, Body 9x9mm, Pitch 0.5mm, IPC Low Density)
pins: 1 NC, 2 PE0 (RXD0/PDI) (io), 3 PE1 (TXD0/PDO) (io), 4 PE2 (XCK0/AIN0) (io), 5 PE3 (OC3A/AIN1) (io), 6 PE4 (OC3B/INT4) (io), 7 PE5 (OC3C/INT5) (io), 8 PE6 (T3/INT6) (io), 9 PE7 (ICP3/INT7) (io), 10 PB0 (~{SS}) (io), 11 PB1 (SCK) (io), 12 PB2 (MOSI) (io), 13 PB3 (MISO) (io), 14 PB4 (OC2A) (io), 15 PB5 (OC1A) (io), 16 PB6 (OC1B) (io), 17 PB7 (OC0A/OC1C) (io), 18 PG3 (TOSC2) (io), 19 PG4 (TOSC1) (io), 20 ~{RESET} (in), 21 VCC (power), 22 GND (power), 23 XTAL2 (out), 24 XTAL1 (in), 25 PD0 (SCL/INT0) (io), 26 PD1 (SDA/INT1) (io), 27 PD2 (RXD1/INT2) (io), 28 PD3 (TXD1/INT3) (io), 29 PD4 (ICP1) (io), 30 PD5 (TXCAN/XCK1) (io), 31 PD6 (RXCAN/T1) (io), 32 PD7 (T0) (io), 33 PG0 (~{WR}) (io), 34 PG1 (~{RD}) (io), 35 PC0 (A8) (io), 36 PC1 (A9) (io), 37 PC2 (A10) (io), 38 PC3 (A11) (io), 39 PC4 (A12) (io), 40 PC5 (A13) (io), 41 PC6 (A14) (io), 42 PC7 (A15/CLKO) (io), 43 PG2 (ALE) (io), 44 PA7 (AD7) (io), 45 PA6 (AD6) (io), 46 PA5 (AD5) (io), 47 PA4 (AD4) (io), 48 PA3 (AD3) (io), 49 PA2 (AD2) (io), 50 PA1 (AD1) (io), 51 PA0 (AD0) (io), 52 VCC (power), 53 GND (power), 54 PF7 (ADC7/TDI) (io), 55 PF6 (ADC6/TDO) (io), 56 PF5 (ADC5/TMS) (io), 57 PF4 (ADC4/TCK) (io), 58 PF3 (ADC3) (io), 59 PF2 (ADC2) (io), 60 PF1 (ADC1) (io), 61 PF0 (ADC0) (io), 62 AREF (power), 63 GND (power), 64 AVCC (power), 65 DAP (power)

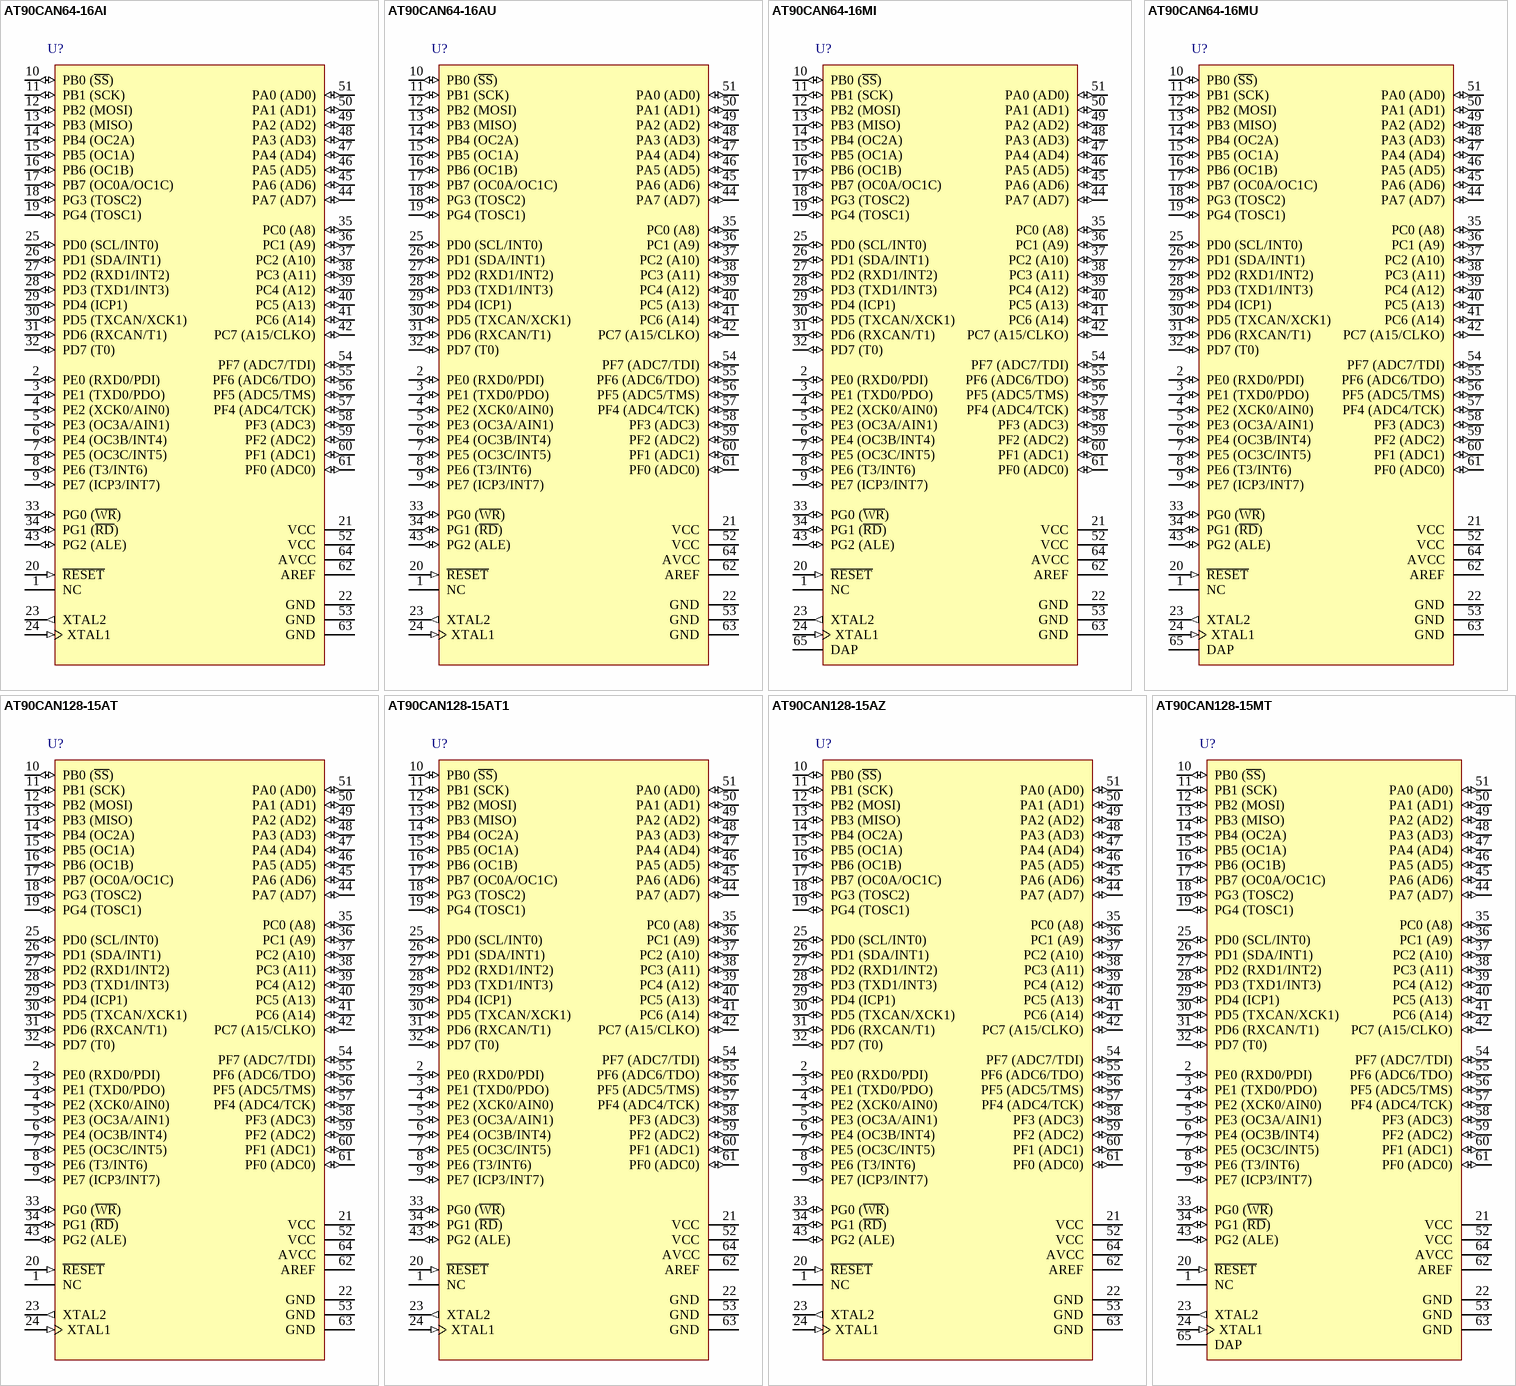
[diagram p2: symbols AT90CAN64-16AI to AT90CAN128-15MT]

## AT90CAN64-16AI
designator U?
8-bit AVR Microcontroller, 64KB Flash and CAN Controller, 53 GPIO pins, Industrial Grade (-40° to +85°C), 64-pin LQFP
footprint 64A_N (Thin QFP, 64-Leads, Body 14x14mm, Pitch 0.8mm, IPC Medium Density)
footprint 64A_L (Thin QFP, 64-Leads, Body 14x14mm, Pitch 0.8mm, IPC High Density)
footprint 64A_M (Thin QFP, 64-Leads, Body 14x14mm, Pitch 0.8mm, IPC Low Density)
pins: 1 NC, 2 PE0 (RXD0/PDI) (io), 3 PE1 (TXD0/PDO) (io), 4 PE2 (XCK0/AIN0) (io), 5 PE3 (OC3A/AIN1) (io), 6 PE4 (OC3B/INT4) (io), 7 PE5 (OC3C/INT5) (io), 8 PE6 (T3/INT6) (io), 9 PE7 (ICP3/INT7) (io), 10 PB0 (~{SS}) (io), 11 PB1 (SCK) (io), 12 PB2 (MOSI) (io), 13 PB3 (MISO) (io), 14 PB4 (OC2A) (io), 15 PB5 (OC1A) (io), 16 PB6 (OC1B) (io), 17 PB7 (OC0A/OC1C) (io), 18 PG3 (TOSC2) (io), 19 PG4 (TOSC1) (io), 20 ~{RESET} (in), 21 VCC (power), 22 GND (power), 23 XTAL2 (out), 24 XTAL1 (in), 25 PD0 (SCL/INT0) (io), 26 PD1 (SDA/INT1) (io), 27 PD2 (RXD1/INT2) (io), 28 PD3 (TXD1/INT3) (io), 29 PD4 (ICP1) (io), 30 PD5 (TXCAN/XCK1) (io), 31 PD6 (RXCAN/T1) (io), 32 PD7 (T0) (io), 33 PG0 (~{WR}) (io), 34 PG1 (~{RD}) (io), 35 PC0 (A8) (io), 36 PC1 (A9) (io), 37 PC2 (A10) (io), 38 PC3 (A11) (io), 39 PC4 (A12) (io), 40 PC5 (A13) (io), 41 PC6 (A14) (io), 42 PC7 (A15/CLKO) (io), 43 PG2 (ALE) (io), 44 PA7 (AD7) (io), 45 PA6 (AD6) (io), 46 PA5 (AD5) (io), 47 PA4 (AD4) (io), 48 PA3 (AD3) (io), 49 PA2 (AD2) (io), 50 PA1 (AD1) (io), 51 PA0 (AD0) (io), 52 VCC (power), 53 GND (power), 54 PF7 (ADC7/TDI) (io), 55 PF6 (ADC6/TDO) (io), 56 PF5 (ADC5/TMS) (io), 57 PF4 (ADC4/TCK) (io), 58 PF3 (ADC3) (io), 59 PF2 (ADC2) (io), 60 PF1 (ADC1) (io), 61 PF0 (ADC0) (io), 62 AREF (power), 63 GND (power), 64 AVCC (power)

## AT90CAN64-16AU
designator U?
8-bit AVR Microcontroller, 64KB Flash and CAN Controller, 53 GPIO pins, Industrial Grade (-40° to +85°C), 64-pin LQFP, Green
footprint 64A_N (Thin QFP, 64-Leads, Body 14x14mm, Pitch 0.8mm, IPC Medium Density)
footprint 64A_L (Thin QFP, 64-Leads, Body 14x14mm, Pitch 0.8mm, IPC High Density)
footprint 64A_M (Thin QFP, 64-Leads, Body 14x14mm, Pitch 0.8mm, IPC Low Density)
pins: 1 NC, 2 PE0 (RXD0/PDI) (io), 3 PE1 (TXD0/PDO) (io), 4 PE2 (XCK0/AIN0) (io), 5 PE3 (OC3A/AIN1) (io), 6 PE4 (OC3B/INT4) (io), 7 PE5 (OC3C/INT5) (io), 8 PE6 (T3/INT6) (io), 9 PE7 (ICP3/INT7) (io), 10 PB0 (~{SS}) (io), 11 PB1 (SCK) (io), 12 PB2 (MOSI) (io), 13 PB3 (MISO) (io), 14 PB4 (OC2A) (io), 15 PB5 (OC1A) (io), 16 PB6 (OC1B) (io), 17 PB7 (OC0A/OC1C) (io), 18 PG3 (TOSC2) (io), 19 PG4 (TOSC1) (io), 20 ~{RESET} (in), 21 VCC (power), 22 GND (power), 23 XTAL2 (out), 24 XTAL1 (in), 25 PD0 (SCL/INT0) (io), 26 PD1 (SDA/INT1) (io), 27 PD2 (RXD1/INT2) (io), 28 PD3 (TXD1/INT3) (io), 29 PD4 (ICP1) (io), 30 PD5 (TXCAN/XCK1) (io), 31 PD6 (RXCAN/T1) (io), 32 PD7 (T0) (io), 33 PG0 (~{WR}) (io), 34 PG1 (~{RD}) (io), 35 PC0 (A8) (io), 36 PC1 (A9) (io), 37 PC2 (A10) (io), 38 PC3 (A11) (io), 39 PC4 (A12) (io), 40 PC5 (A13) (io), 41 PC6 (A14) (io), 42 PC7 (A15/CLKO) (io), 43 PG2 (ALE) (io), 44 PA7 (AD7) (io), 45 PA6 (AD6) (io), 46 PA5 (AD5) (io), 47 PA4 (AD4) (io), 48 PA3 (AD3) (io), 49 PA2 (AD2) (io), 50 PA1 (AD1) (io), 51 PA0 (AD0) (io), 52 VCC (power), 53 GND (power), 54 PF7 (ADC7/TDI) (io), 55 PF6 (ADC6/TDO) (io), 56 PF5 (ADC5/TMS) (io), 57 PF4 (ADC4/TCK) (io), 58 PF3 (ADC3) (io), 59 PF2 (ADC2) (io), 60 PF1 (ADC1) (io), 61 PF0 (ADC0) (io), 62 AREF (power), 63 GND (power), 64 AVCC (power)

## AT90CAN64-16MI
designator U?
8-bit AVR Microcontroller, 64KB Flash and CAN Controller, 53 GPIO pins, Industrial Grade (-40° to +85°C), 64-pin VQFN
footprint Z64-2_N (QFN, 64-Leads, Body 9x9mm, Pitch 0.5mm, IPC Medium Density)
footprint Z64-2_L (QFN, 64-Leads, Body 9x9mm, Pitch 0.5mm, IPC High Density)
footprint Z64-2_M (QFN, 64-Leads, Body 9x9mm, Pitch 0.5mm, IPC Low Density)
pins: 1 NC, 2 PE0 (RXD0/PDI) (io), 3 PE1 (TXD0/PDO) (io), 4 PE2 (XCK0/AIN0) (io), 5 PE3 (OC3A/AIN1) (io), 6 PE4 (OC3B/INT4) (io), 7 PE5 (OC3C/INT5) (io), 8 PE6 (T3/INT6) (io), 9 PE7 (ICP3/INT7) (io), 10 PB0 (~{SS}) (io), 11 PB1 (SCK) (io), 12 PB2 (MOSI) (io), 13 PB3 (MISO) (io), 14 PB4 (OC2A) (io), 15 PB5 (OC1A) (io), 16 PB6 (OC1B) (io), 17 PB7 (OC0A/OC1C) (io), 18 PG3 (TOSC2) (io), 19 PG4 (TOSC1) (io), 20 ~{RESET} (in), 21 VCC (power), 22 GND (power), 23 XTAL2 (out), 24 XTAL1 (in), 25 PD0 (SCL/INT0) (io), 26 PD1 (SDA/INT1) (io), 27 PD2 (RXD1/INT2) (io), 28 PD3 (TXD1/INT3) (io), 29 PD4 (ICP1) (io), 30 PD5 (TXCAN/XCK1) (io), 31 PD6 (RXCAN/T1) (io), 32 PD7 (T0) (io), 33 PG0 (~{WR}) (io), 34 PG1 (~{RD}) (io), 35 PC0 (A8) (io), 36 PC1 (A9) (io), 37 PC2 (A10) (io), 38 PC3 (A11) (io), 39 PC4 (A12) (io), 40 PC5 (A13) (io), 41 PC6 (A14) (io), 42 PC7 (A15/CLKO) (io), 43 PG2 (ALE) (io), 44 PA7 (AD7) (io), 45 PA6 (AD6) (io), 46 PA5 (AD5) (io), 47 PA4 (AD4) (io), 48 PA3 (AD3) (io), 49 PA2 (AD2) (io), 50 PA1 (AD1) (io), 51 PA0 (AD0) (io), 52 VCC (power), 53 GND (power), 54 PF7 (ADC7/TDI) (io), 55 PF6 (ADC6/TDO) (io), 56 PF5 (ADC5/TMS) (io), 57 PF4 (ADC4/TCK) (io), 58 PF3 (ADC3) (io), 59 PF2 (ADC2) (io), 60 PF1 (ADC1) (io), 61 PF0 (ADC0) (io), 62 AREF (power), 63 GND (power), 64 AVCC (power), 65 DAP (power)

## AT90CAN64-16MU
designator U?
8-bit AVR Microcontroller, 64KB Flash and CAN Controller, 53 GPIO pins, Industrial Grade (-40° to +85°C), 64-pin VQFN, Green
footprint Z64-2_N (QFN, 64-Leads, Body 9x9mm, Pitch 0.5mm, IPC Medium Density)
footprint Z64-2_L (QFN, 64-Leads, Body 9x9mm, Pitch 0.5mm, IPC High Density)
footprint Z64-2_M (QFN, 64-Leads, Body 9x9mm, Pitch 0.5mm, IPC Low Density)
pins: 1 NC, 2 PE0 (RXD0/PDI) (io), 3 PE1 (TXD0/PDO) (io), 4 PE2 (XCK0/AIN0) (io), 5 PE3 (OC3A/AIN1) (io), 6 PE4 (OC3B/INT4) (io), 7 PE5 (OC3C/INT5) (io), 8 PE6 (T3/INT6) (io), 9 PE7 (ICP3/INT7) (io), 10 PB0 (~{SS}) (io), 11 PB1 (SCK) (io), 12 PB2 (MOSI) (io), 13 PB3 (MISO) (io), 14 PB4 (OC2A) (io), 15 PB5 (OC1A) (io), 16 PB6 (OC1B) (io), 17 PB7 (OC0A/OC1C) (io), 18 PG3 (TOSC2) (io), 19 PG4 (TOSC1) (io), 20 ~{RESET} (in), 21 VCC (power), 22 GND (power), 23 XTAL2 (out), 24 XTAL1 (in), 25 PD0 (SCL/INT0) (io), 26 PD1 (SDA/INT1) (io), 27 PD2 (RXD1/INT2) (io), 28 PD3 (TXD1/INT3) (io), 29 PD4 (ICP1) (io), 30 PD5 (TXCAN/XCK1) (io), 31 PD6 (RXCAN/T1) (io), 32 PD7 (T0) (io), 33 PG0 (~{WR}) (io), 34 PG1 (~{RD}) (io), 35 PC0 (A8) (io), 36 PC1 (A9) (io), 37 PC2 (A10) (io), 38 PC3 (A11) (io), 39 PC4 (A12) (io), 40 PC5 (A13) (io), 41 PC6 (A14) (io), 42 PC7 (A15/CLKO) (io), 43 PG2 (ALE) (io), 44 PA7 (AD7) (io), 45 PA6 (AD6) (io), 46 PA5 (AD5) (io), 47 PA4 (AD4) (io), 48 PA3 (AD3) (io), 49 PA2 (AD2) (io), 50 PA1 (AD1) (io), 51 PA0 (AD0) (io), 52 VCC (power), 53 GND (power), 54 PF7 (ADC7/TDI) (io), 55 PF6 (ADC6/TDO) (io), 56 PF5 (ADC5/TMS) (io), 57 PF4 (ADC4/TCK) (io), 58 PF3 (ADC3) (io), 59 PF2 (ADC2) (io), 60 PF1 (ADC1) (io), 61 PF0 (ADC0) (io), 62 AREF (power), 63 GND (power), 64 AVCC (power), 65 DAP (power)

## AT90CAN128-15AT
designator U?
8-bit Automotive AVR Microcontroller, 128KB Flash and CAN Controller, 53 GPIO pins, Automotive Grade (-40°to +85°C), 64-pin LQFP
footprint 64A_N (Thin QFP, 64-Leads, Body 14x14mm, Pitch 0.8mm, IPC Medium Density)
footprint 64A_L (Thin QFP, 64-Leads, Body 14x14mm, Pitch 0.8mm, IPC High Density)
footprint 64A_M (Thin QFP, 64-Leads, Body 14x14mm, Pitch 0.8mm, IPC Low Density)
pins: 1 NC, 2 PE0 (RXD0/PDI) (io), 3 PE1 (TXD0/PDO) (io), 4 PE2 (XCK0/AIN0) (io), 5 PE3 (OC3A/AIN1) (io), 6 PE4 (OC3B/INT4) (io), 7 PE5 (OC3C/INT5) (io), 8 PE6 (T3/INT6) (io), 9 PE7 (ICP3/INT7) (io), 10 PB0 (~{SS}) (io), 11 PB1 (SCK) (io), 12 PB2 (MOSI) (io), 13 PB3 (MISO) (io), 14 PB4 (OC2A) (io), 15 PB5 (OC1A) (io), 16 PB6 (OC1B) (io), 17 PB7 (OC0A/OC1C) (io), 18 PG3 (TOSC2) (io), 19 PG4 (TOSC1) (io), 20 ~{RESET} (in), 21 VCC (power), 22 GND (power), 23 XTAL2 (out), 24 XTAL1 (in), 25 PD0 (SCL/INT0) (io), 26 PD1 (SDA/INT1) (io), 27 PD2 (RXD1/INT2) (io), 28 PD3 (TXD1/INT3) (io), 29 PD4 (ICP1) (io), 30 PD5 (TXCAN/XCK1) (io), 31 PD6 (RXCAN/T1) (io), 32 PD7 (T0) (io), 33 PG0 (~{WR}) (io), 34 PG1 (~{RD}) (io), 35 PC0 (A8) (io), 36 PC1 (A9) (io), 37 PC2 (A10) (io), 38 PC3 (A11) (io), 39 PC4 (A12) (io), 40 PC5 (A13) (io), 41 PC6 (A14) (io), 42 PC7 (A15/CLKO) (io), 43 PG2 (ALE) (io), 44 PA7 (AD7) (io), 45 PA6 (AD6) (io), 46 PA5 (AD5) (io), 47 PA4 (AD4) (io), 48 PA3 (AD3) (io), 49 PA2 (AD2) (io), 50 PA1 (AD1) (io), 51 PA0 (AD0) (io), 52 VCC (power), 53 GND (power), 54 PF7 (ADC7/TDI) (io), 55 PF6 (ADC6/TDO) (io), 56 PF5 (ADC5/TMS) (io), 57 PF4 (ADC4/TCK) (io), 58 PF3 (ADC3) (io), 59 PF2 (ADC2) (io), 60 PF1 (ADC1) (io), 61 PF0 (ADC0) (io), 62 AREF (power), 63 GND (power), 64 AVCC (power)

## AT90CAN128-15AT1
designator U?
8-bit Automotive AVR Microcontroller, 128KB Flash and CAN Controller, 53 GPIO pins, Automotive Grade (-40°to +105°C), 64-pin LQFP
footprint 64A_N (Thin QFP, 64-Leads, Body 14x14mm, Pitch 0.8mm, IPC Medium Density)
footprint 64A_L (Thin QFP, 64-Leads, Body 14x14mm, Pitch 0.8mm, IPC High Density)
footprint 64A_M (Thin QFP, 64-Leads, Body 14x14mm, Pitch 0.8mm, IPC Low Density)
pins: 1 NC, 2 PE0 (RXD0/PDI) (io), 3 PE1 (TXD0/PDO) (io), 4 PE2 (XCK0/AIN0) (io), 5 PE3 (OC3A/AIN1) (io), 6 PE4 (OC3B/INT4) (io), 7 PE5 (OC3C/INT5) (io), 8 PE6 (T3/INT6) (io), 9 PE7 (ICP3/INT7) (io), 10 PB0 (~{SS}) (io), 11 PB1 (SCK) (io), 12 PB2 (MOSI) (io), 13 PB3 (MISO) (io), 14 PB4 (OC2A) (io), 15 PB5 (OC1A) (io), 16 PB6 (OC1B) (io), 17 PB7 (OC0A/OC1C) (io), 18 PG3 (TOSC2) (io), 19 PG4 (TOSC1) (io), 20 ~{RESET} (in), 21 VCC (power), 22 GND (power), 23 XTAL2 (out), 24 XTAL1 (in), 25 PD0 (SCL/INT0) (io), 26 PD1 (SDA/INT1) (io), 27 PD2 (RXD1/INT2) (io), 28 PD3 (TXD1/INT3) (io), 29 PD4 (ICP1) (io), 30 PD5 (TXCAN/XCK1) (io), 31 PD6 (RXCAN/T1) (io), 32 PD7 (T0) (io), 33 PG0 (~{WR}) (io), 34 PG1 (~{RD}) (io), 35 PC0 (A8) (io), 36 PC1 (A9) (io), 37 PC2 (A10) (io), 38 PC3 (A11) (io), 39 PC4 (A12) (io), 40 PC5 (A13) (io), 41 PC6 (A14) (io), 42 PC7 (A15/CLKO) (io), 43 PG2 (ALE) (io), 44 PA7 (AD7) (io), 45 PA6 (AD6) (io), 46 PA5 (AD5) (io), 47 PA4 (AD4) (io), 48 PA3 (AD3) (io), 49 PA2 (AD2) (io), 50 PA1 (AD1) (io), 51 PA0 (AD0) (io), 52 VCC (power), 53 GND (power), 54 PF7 (ADC7/TDI) (io), 55 PF6 (ADC6/TDO) (io), 56 PF5 (ADC5/TMS) (io), 57 PF4 (ADC4/TCK) (io), 58 PF3 (ADC3) (io), 59 PF2 (ADC2) (io), 60 PF1 (ADC1) (io), 61 PF0 (ADC0) (io), 62 AREF (power), 63 GND (power), 64 AVCC (power)

## AT90CAN128-15AZ
designator U?
8-bit Automotive AVR Microcontroller, 128KB Flash and CAN Controller, 53 GPIO pins, Automotive Grade (-40°to +125°C), 64-pin LQFP
footprint 64A_N (Thin QFP, 64-Leads, Body 14x14mm, Pitch 0.8mm, IPC Medium Density)
footprint 64A_L (Thin QFP, 64-Leads, Body 14x14mm, Pitch 0.8mm, IPC High Density)
footprint 64A_M (Thin QFP, 64-Leads, Body 14x14mm, Pitch 0.8mm, IPC Low Density)
pins: 1 NC, 2 PE0 (RXD0/PDI) (io), 3 PE1 (TXD0/PDO) (io), 4 PE2 (XCK0/AIN0) (io), 5 PE3 (OC3A/AIN1) (io), 6 PE4 (OC3B/INT4) (io), 7 PE5 (OC3C/INT5) (io), 8 PE6 (T3/INT6) (io), 9 PE7 (ICP3/INT7) (io), 10 PB0 (~{SS}) (io), 11 PB1 (SCK) (io), 12 PB2 (MOSI) (io), 13 PB3 (MISO) (io), 14 PB4 (OC2A) (io), 15 PB5 (OC1A) (io), 16 PB6 (OC1B) (io), 17 PB7 (OC0A/OC1C) (io), 18 PG3 (TOSC2) (io), 19 PG4 (TOSC1) (io), 20 ~{RESET} (in), 21 VCC (power), 22 GND (power), 23 XTAL2 (out), 24 XTAL1 (in), 25 PD0 (SCL/INT0) (io), 26 PD1 (SDA/INT1) (io), 27 PD2 (RXD1/INT2) (io), 28 PD3 (TXD1/INT3) (io), 29 PD4 (ICP1) (io), 30 PD5 (TXCAN/XCK1) (io), 31 PD6 (RXCAN/T1) (io), 32 PD7 (T0) (io), 33 PG0 (~{WR}) (io), 34 PG1 (~{RD}) (io), 35 PC0 (A8) (io), 36 PC1 (A9) (io), 37 PC2 (A10) (io), 38 PC3 (A11) (io), 39 PC4 (A12) (io), 40 PC5 (A13) (io), 41 PC6 (A14) (io), 42 PC7 (A15/CLKO) (io), 43 PG2 (ALE) (io), 44 PA7 (AD7) (io), 45 PA6 (AD6) (io), 46 PA5 (AD5) (io), 47 PA4 (AD4) (io), 48 PA3 (AD3) (io), 49 PA2 (AD2) (io), 50 PA1 (AD1) (io), 51 PA0 (AD0) (io), 52 VCC (power), 53 GND (power), 54 PF7 (ADC7/TDI) (io), 55 PF6 (ADC6/TDO) (io), 56 PF5 (ADC5/TMS) (io), 57 PF4 (ADC4/TCK) (io), 58 PF3 (ADC3) (io), 59 PF2 (ADC2) (io), 60 PF1 (ADC1) (io), 61 PF0 (ADC0) (io), 62 AREF (power), 63 GND (power), 64 AVCC (power)

## AT90CAN128-15MT
designator U?
8-bit Automotive AVR Microcontroller, 128KB Flash and CAN Controller, 53 GPIO pins, Automotive Grade (-40°to +85°C), 64-Pin VQFN
footprint Z64-2_N (QFN, 64-Leads, Body 9x9mm, Pitch 0.5mm, IPC Medium Density)
footprint Z64-2_L (QFN, 64-Leads, Body 9x9mm, Pitch 0.5mm, IPC High Density)
footprint Z64-2_M (QFN, 64-Leads, Body 9x9mm, Pitch 0.5mm, IPC Low Density)
pins: 1 NC, 2 PE0 (RXD0/PDI) (io), 3 PE1 (TXD0/PDO) (io), 4 PE2 (XCK0/AIN0) (io), 5 PE3 (OC3A/AIN1) (io), 6 PE4 (OC3B/INT4) (io), 7 PE5 (OC3C/INT5) (io), 8 PE6 (T3/INT6) (io), 9 PE7 (ICP3/INT7) (io), 10 PB0 (~{SS}) (io), 11 PB1 (SCK) (io), 12 PB2 (MOSI) (io), 13 PB3 (MISO) (io), 14 PB4 (OC2A) (io), 15 PB5 (OC1A) (io), 16 PB6 (OC1B) (io), 17 PB7 (OC0A/OC1C) (io), 18 PG3 (TOSC2) (io), 19 PG4 (TOSC1) (io), 20 ~{RESET} (in), 21 VCC (power), 22 GND (power), 23 XTAL2 (out), 24 XTAL1 (in), 25 PD0 (SCL/INT0) (io), 26 PD1 (SDA/INT1) (io), 27 PD2 (RXD1/INT2) (io), 28 PD3 (TXD1/INT3) (io), 29 PD4 (ICP1) (io), 30 PD5 (TXCAN/XCK1) (io), 31 PD6 (RXCAN/T1) (io), 32 PD7 (T0) (io), 33 PG0 (~{WR}) (io), 34 PG1 (~{RD}) (io), 35 PC0 (A8) (io), 36 PC1 (A9) (io), 37 PC2 (A10) (io), 38 PC3 (A11) (io), 39 PC4 (A12) (io), 40 PC5 (A13) (io), 41 PC6 (A14) (io), 42 PC7 (A15/CLKO) (io), 43 PG2 (ALE) (io), 44 PA7 (AD7) (io), 45 PA6 (AD6) (io), 46 PA5 (AD5) (io), 47 PA4 (AD4) (io), 48 PA3 (AD3) (io), 49 PA2 (AD2) (io), 50 PA1 (AD1) (io), 51 PA0 (AD0) (io), 52 VCC (power), 53 GND (power), 54 PF7 (ADC7/TDI) (io), 55 PF6 (ADC6/TDO) (io), 56 PF5 (ADC5/TMS) (io), 57 PF4 (ADC4/TCK) (io), 58 PF3 (ADC3) (io), 59 PF2 (ADC2) (io), 60 PF1 (ADC1) (io), 61 PF0 (ADC0) (io), 62 AREF (power), 63 GND (power), 64 AVCC (power), 65 DAP (power)

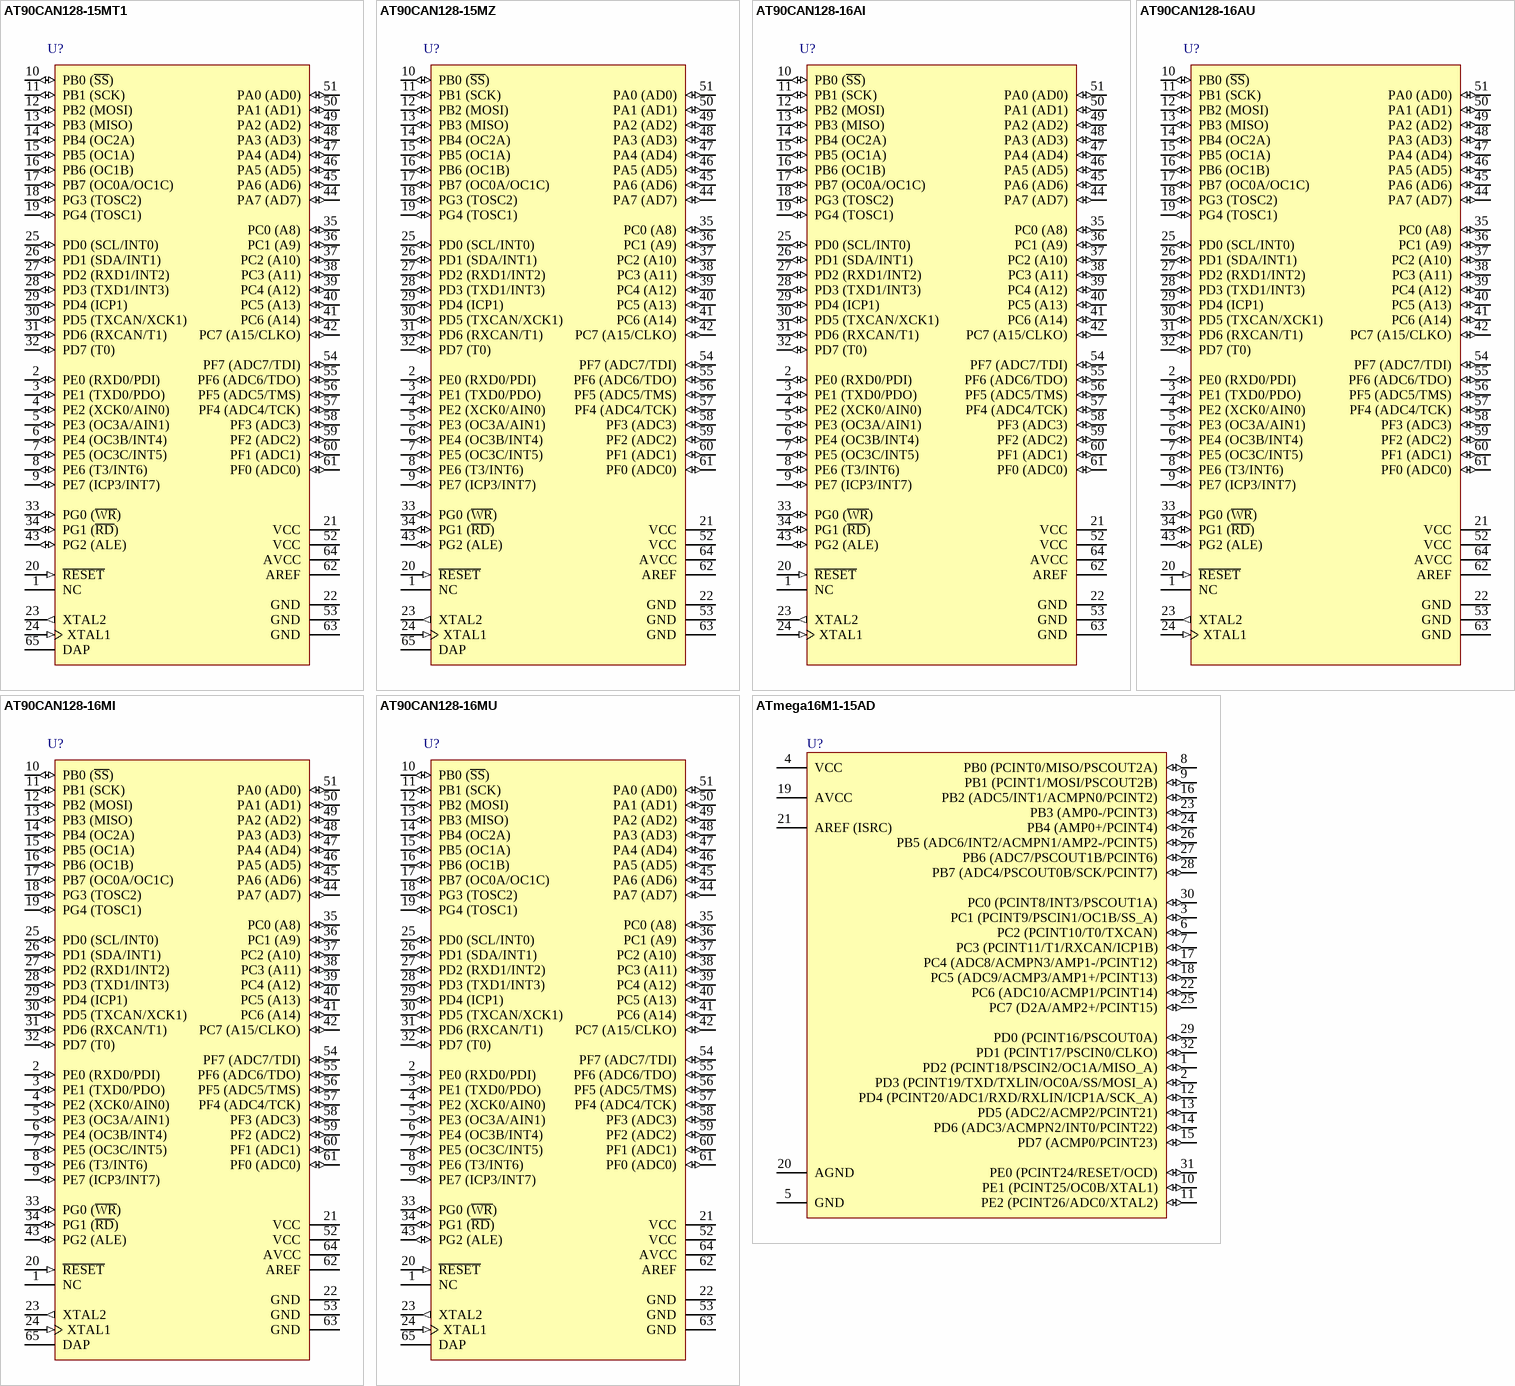
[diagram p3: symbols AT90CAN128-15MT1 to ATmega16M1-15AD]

## AT90CAN128-15MT1
designator U?
8-bit Automotive AVR Microcontroller, 128KB Flash and CAN Controller, 53 GPIO pins, Automotive Grade (-40°to +105C), 64-Pin VQFN
footprint Z64-2_N (QFN, 64-Leads, Body 9x9mm, Pitch 0.5mm, IPC Medium Density)
footprint Z64-2_L (QFN, 64-Leads, Body 9x9mm, Pitch 0.5mm, IPC High Density)
footprint Z64-2_M (QFN, 64-Leads, Body 9x9mm, Pitch 0.5mm, IPC Low Density)
pins: 1 NC, 2 PE0 (RXD0/PDI) (io), 3 PE1 (TXD0/PDO) (io), 4 PE2 (XCK0/AIN0) (io), 5 PE3 (OC3A/AIN1) (io), 6 PE4 (OC3B/INT4) (io), 7 PE5 (OC3C/INT5) (io), 8 PE6 (T3/INT6) (io), 9 PE7 (ICP3/INT7) (io), 10 PB0 (~{SS}) (io), 11 PB1 (SCK) (io), 12 PB2 (MOSI) (io), 13 PB3 (MISO) (io), 14 PB4 (OC2A) (io), 15 PB5 (OC1A) (io), 16 PB6 (OC1B) (io), 17 PB7 (OC0A/OC1C) (io), 18 PG3 (TOSC2) (io), 19 PG4 (TOSC1) (io), 20 ~{RESET} (in), 21 VCC (power), 22 GND (power), 23 XTAL2 (out), 24 XTAL1 (in), 25 PD0 (SCL/INT0) (io), 26 PD1 (SDA/INT1) (io), 27 PD2 (RXD1/INT2) (io), 28 PD3 (TXD1/INT3) (io), 29 PD4 (ICP1) (io), 30 PD5 (TXCAN/XCK1) (io), 31 PD6 (RXCAN/T1) (io), 32 PD7 (T0) (io), 33 PG0 (~{WR}) (io), 34 PG1 (~{RD}) (io), 35 PC0 (A8) (io), 36 PC1 (A9) (io), 37 PC2 (A10) (io), 38 PC3 (A11) (io), 39 PC4 (A12) (io), 40 PC5 (A13) (io), 41 PC6 (A14) (io), 42 PC7 (A15/CLKO) (io), 43 PG2 (ALE) (io), 44 PA7 (AD7) (io), 45 PA6 (AD6) (io), 46 PA5 (AD5) (io), 47 PA4 (AD4) (io), 48 PA3 (AD3) (io), 49 PA2 (AD2) (io), 50 PA1 (AD1) (io), 51 PA0 (AD0) (io), 52 VCC (power), 53 GND (power), 54 PF7 (ADC7/TDI) (io), 55 PF6 (ADC6/TDO) (io), 56 PF5 (ADC5/TMS) (io), 57 PF4 (ADC4/TCK) (io), 58 PF3 (ADC3) (io), 59 PF2 (ADC2) (io), 60 PF1 (ADC1) (io), 61 PF0 (ADC0) (io), 62 AREF (power), 63 GND (power), 64 AVCC (power), 65 DAP (power)

## AT90CAN128-15MZ
designator U?
8-bit Automotive AVR Microcontroller, 128KB Flash and CAN Controller, 53 GPIO pins, Automotive Grade (-40°to +125°C), 64-Pin VQFN
footprint Z64-2_N (QFN, 64-Leads, Body 9x9mm, Pitch 0.5mm, IPC Medium Density)
footprint Z64-2_L (QFN, 64-Leads, Body 9x9mm, Pitch 0.5mm, IPC High Density)
footprint Z64-2_M (QFN, 64-Leads, Body 9x9mm, Pitch 0.5mm, IPC Low Density)
pins: 1 NC, 2 PE0 (RXD0/PDI) (io), 3 PE1 (TXD0/PDO) (io), 4 PE2 (XCK0/AIN0) (io), 5 PE3 (OC3A/AIN1) (io), 6 PE4 (OC3B/INT4) (io), 7 PE5 (OC3C/INT5) (io), 8 PE6 (T3/INT6) (io), 9 PE7 (ICP3/INT7) (io), 10 PB0 (~{SS}) (io), 11 PB1 (SCK) (io), 12 PB2 (MOSI) (io), 13 PB3 (MISO) (io), 14 PB4 (OC2A) (io), 15 PB5 (OC1A) (io), 16 PB6 (OC1B) (io), 17 PB7 (OC0A/OC1C) (io), 18 PG3 (TOSC2) (io), 19 PG4 (TOSC1) (io), 20 ~{RESET} (in), 21 VCC (power), 22 GND (power), 23 XTAL2 (out), 24 XTAL1 (in), 25 PD0 (SCL/INT0) (io), 26 PD1 (SDA/INT1) (io), 27 PD2 (RXD1/INT2) (io), 28 PD3 (TXD1/INT3) (io), 29 PD4 (ICP1) (io), 30 PD5 (TXCAN/XCK1) (io), 31 PD6 (RXCAN/T1) (io), 32 PD7 (T0) (io), 33 PG0 (~{WR}) (io), 34 PG1 (~{RD}) (io), 35 PC0 (A8) (io), 36 PC1 (A9) (io), 37 PC2 (A10) (io), 38 PC3 (A11) (io), 39 PC4 (A12) (io), 40 PC5 (A13) (io), 41 PC6 (A14) (io), 42 PC7 (A15/CLKO) (io), 43 PG2 (ALE) (io), 44 PA7 (AD7) (io), 45 PA6 (AD6) (io), 46 PA5 (AD5) (io), 47 PA4 (AD4) (io), 48 PA3 (AD3) (io), 49 PA2 (AD2) (io), 50 PA1 (AD1) (io), 51 PA0 (AD0) (io), 52 VCC (power), 53 GND (power), 54 PF7 (ADC7/TDI) (io), 55 PF6 (ADC6/TDO) (io), 56 PF5 (ADC5/TMS) (io), 57 PF4 (ADC4/TCK) (io), 58 PF3 (ADC3) (io), 59 PF2 (ADC2) (io), 60 PF1 (ADC1) (io), 61 PF0 (ADC0) (io), 62 AREF (power), 63 GND (power), 64 AVCC (power), 65 DAP (power)

## AT90CAN128-16AI
designator U?
8-bit AVR Microcontroller, 128KB Flash and CAN Controller, 53 GPIO pins, Industrial Grade (-40° to +85°C), 64-pin LQFP
footprint 64A_N (Thin QFP, 64-Leads, Body 14x14mm, Pitch 0.8mm, IPC Medium Density)
footprint 64A_L (Thin QFP, 64-Leads, Body 14x14mm, Pitch 0.8mm, IPC High Density)
footprint 64A_M (Thin QFP, 64-Leads, Body 14x14mm, Pitch 0.8mm, IPC Low Density)
pins: 1 NC, 2 PE0 (RXD0/PDI) (io), 3 PE1 (TXD0/PDO) (io), 4 PE2 (XCK0/AIN0) (io), 5 PE3 (OC3A/AIN1) (io), 6 PE4 (OC3B/INT4) (io), 7 PE5 (OC3C/INT5) (io), 8 PE6 (T3/INT6) (io), 9 PE7 (ICP3/INT7) (io), 10 PB0 (~{SS}) (io), 11 PB1 (SCK) (io), 12 PB2 (MOSI) (io), 13 PB3 (MISO) (io), 14 PB4 (OC2A) (io), 15 PB5 (OC1A) (io), 16 PB6 (OC1B) (io), 17 PB7 (OC0A/OC1C) (io), 18 PG3 (TOSC2) (io), 19 PG4 (TOSC1) (io), 20 ~{RESET} (in), 21 VCC (power), 22 GND (power), 23 XTAL2 (out), 24 XTAL1 (in), 25 PD0 (SCL/INT0) (io), 26 PD1 (SDA/INT1) (io), 27 PD2 (RXD1/INT2) (io), 28 PD3 (TXD1/INT3) (io), 29 PD4 (ICP1) (io), 30 PD5 (TXCAN/XCK1) (io), 31 PD6 (RXCAN/T1) (io), 32 PD7 (T0) (io), 33 PG0 (~{WR}) (io), 34 PG1 (~{RD}) (io), 35 PC0 (A8) (io), 36 PC1 (A9) (io), 37 PC2 (A10) (io), 38 PC3 (A11) (io), 39 PC4 (A12) (io), 40 PC5 (A13) (io), 41 PC6 (A14) (io), 42 PC7 (A15/CLKO) (io), 43 PG2 (ALE) (io), 44 PA7 (AD7) (io), 45 PA6 (AD6) (io), 46 PA5 (AD5) (io), 47 PA4 (AD4) (io), 48 PA3 (AD3) (io), 49 PA2 (AD2) (io), 50 PA1 (AD1) (io), 51 PA0 (AD0) (io), 52 VCC (power), 53 GND (power), 54 PF7 (ADC7/TDI) (io), 55 PF6 (ADC6/TDO) (io), 56 PF5 (ADC5/TMS) (io), 57 PF4 (ADC4/TCK) (io), 58 PF3 (ADC3) (io), 59 PF2 (ADC2) (io), 60 PF1 (ADC1) (io), 61 PF0 (ADC0) (io), 62 AREF (power), 63 GND (power), 64 AVCC (power)

## AT90CAN128-16AU
designator U?
8-bit AVR Microcontroller, 128KB Flash and CAN Controller, 53 GPIO pins, Industrial Grade (-40° to +85°C), 64-pin LQFP, Green
footprint 64A_N (Thin QFP, 64-Leads, Body 14x14mm, Pitch 0.8mm, IPC Medium Density)
footprint 64A_L (Thin QFP, 64-Leads, Body 14x14mm, Pitch 0.8mm, IPC High Density)
footprint 64A_M (Thin QFP, 64-Leads, Body 14x14mm, Pitch 0.8mm, IPC Low Density)
pins: 1 NC, 2 PE0 (RXD0/PDI) (io), 3 PE1 (TXD0/PDO) (io), 4 PE2 (XCK0/AIN0) (io), 5 PE3 (OC3A/AIN1) (io), 6 PE4 (OC3B/INT4) (io), 7 PE5 (OC3C/INT5) (io), 8 PE6 (T3/INT6) (io), 9 PE7 (ICP3/INT7) (io), 10 PB0 (~{SS}) (io), 11 PB1 (SCK) (io), 12 PB2 (MOSI) (io), 13 PB3 (MISO) (io), 14 PB4 (OC2A) (io), 15 PB5 (OC1A) (io), 16 PB6 (OC1B) (io), 17 PB7 (OC0A/OC1C) (io), 18 PG3 (TOSC2) (io), 19 PG4 (TOSC1) (io), 20 ~{RESET} (in), 21 VCC (power), 22 GND (power), 23 XTAL2 (out), 24 XTAL1 (in), 25 PD0 (SCL/INT0) (io), 26 PD1 (SDA/INT1) (io), 27 PD2 (RXD1/INT2) (io), 28 PD3 (TXD1/INT3) (io), 29 PD4 (ICP1) (io), 30 PD5 (TXCAN/XCK1) (io), 31 PD6 (RXCAN/T1) (io), 32 PD7 (T0) (io), 33 PG0 (~{WR}) (io), 34 PG1 (~{RD}) (io), 35 PC0 (A8) (io), 36 PC1 (A9) (io), 37 PC2 (A10) (io), 38 PC3 (A11) (io), 39 PC4 (A12) (io), 40 PC5 (A13) (io), 41 PC6 (A14) (io), 42 PC7 (A15/CLKO) (io), 43 PG2 (ALE) (io), 44 PA7 (AD7) (io), 45 PA6 (AD6) (io), 46 PA5 (AD5) (io), 47 PA4 (AD4) (io), 48 PA3 (AD3) (io), 49 PA2 (AD2) (io), 50 PA1 (AD1) (io), 51 PA0 (AD0) (io), 52 VCC (power), 53 GND (power), 54 PF7 (ADC7/TDI) (io), 55 PF6 (ADC6/TDO) (io), 56 PF5 (ADC5/TMS) (io), 57 PF4 (ADC4/TCK) (io), 58 PF3 (ADC3) (io), 59 PF2 (ADC2) (io), 60 PF1 (ADC1) (io), 61 PF0 (ADC0) (io), 62 AREF (power), 63 GND (power), 64 AVCC (power)

## AT90CAN128-16MI
designator U?
8-bit AVR Microcontroller, 128KB Flash and CAN Controller, 53 GPIO pins, Industrial Grade (-40° to +85°C), 64-pin VQFN
footprint Z64-2_N (QFN, 64-Leads, Body 9x9mm, Pitch 0.5mm, IPC Medium Density)
footprint Z64-2_L (QFN, 64-Leads, Body 9x9mm, Pitch 0.5mm, IPC High Density)
footprint Z64-2_M (QFN, 64-Leads, Body 9x9mm, Pitch 0.5mm, IPC Low Density)
pins: 1 NC, 2 PE0 (RXD0/PDI) (io), 3 PE1 (TXD0/PDO) (io), 4 PE2 (XCK0/AIN0) (io), 5 PE3 (OC3A/AIN1) (io), 6 PE4 (OC3B/INT4) (io), 7 PE5 (OC3C/INT5) (io), 8 PE6 (T3/INT6) (io), 9 PE7 (ICP3/INT7) (io), 10 PB0 (~{SS}) (io), 11 PB1 (SCK) (io), 12 PB2 (MOSI) (io), 13 PB3 (MISO) (io), 14 PB4 (OC2A) (io), 15 PB5 (OC1A) (io), 16 PB6 (OC1B) (io), 17 PB7 (OC0A/OC1C) (io), 18 PG3 (TOSC2) (io), 19 PG4 (TOSC1) (io), 20 ~{RESET} (in), 21 VCC (power), 22 GND (power), 23 XTAL2 (out), 24 XTAL1 (in), 25 PD0 (SCL/INT0) (io), 26 PD1 (SDA/INT1) (io), 27 PD2 (RXD1/INT2) (io), 28 PD3 (TXD1/INT3) (io), 29 PD4 (ICP1) (io), 30 PD5 (TXCAN/XCK1) (io), 31 PD6 (RXCAN/T1) (io), 32 PD7 (T0) (io), 33 PG0 (~{WR}) (io), 34 PG1 (~{RD}) (io), 35 PC0 (A8) (io), 36 PC1 (A9) (io), 37 PC2 (A10) (io), 38 PC3 (A11) (io), 39 PC4 (A12) (io), 40 PC5 (A13) (io), 41 PC6 (A14) (io), 42 PC7 (A15/CLKO) (io), 43 PG2 (ALE) (io), 44 PA7 (AD7) (io), 45 PA6 (AD6) (io), 46 PA5 (AD5) (io), 47 PA4 (AD4) (io), 48 PA3 (AD3) (io), 49 PA2 (AD2) (io), 50 PA1 (AD1) (io), 51 PA0 (AD0) (io), 52 VCC (power), 53 GND (power), 54 PF7 (ADC7/TDI) (io), 55 PF6 (ADC6/TDO) (io), 56 PF5 (ADC5/TMS) (io), 57 PF4 (ADC4/TCK) (io), 58 PF3 (ADC3) (io), 59 PF2 (ADC2) (io), 60 PF1 (ADC1) (io), 61 PF0 (ADC0) (io), 62 AREF (power), 63 GND (power), 64 AVCC (power), 65 DAP (power)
